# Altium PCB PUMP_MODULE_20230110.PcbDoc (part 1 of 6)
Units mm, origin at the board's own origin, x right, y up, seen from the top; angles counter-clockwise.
Board outline 260.15 x 142.01 mm, 4 copper layers (Top Layer, Mid-Layer 1, Mid-Layer 2, Bottom Layer); 422 components, 240 nets, 1746 pads, 416 vias.
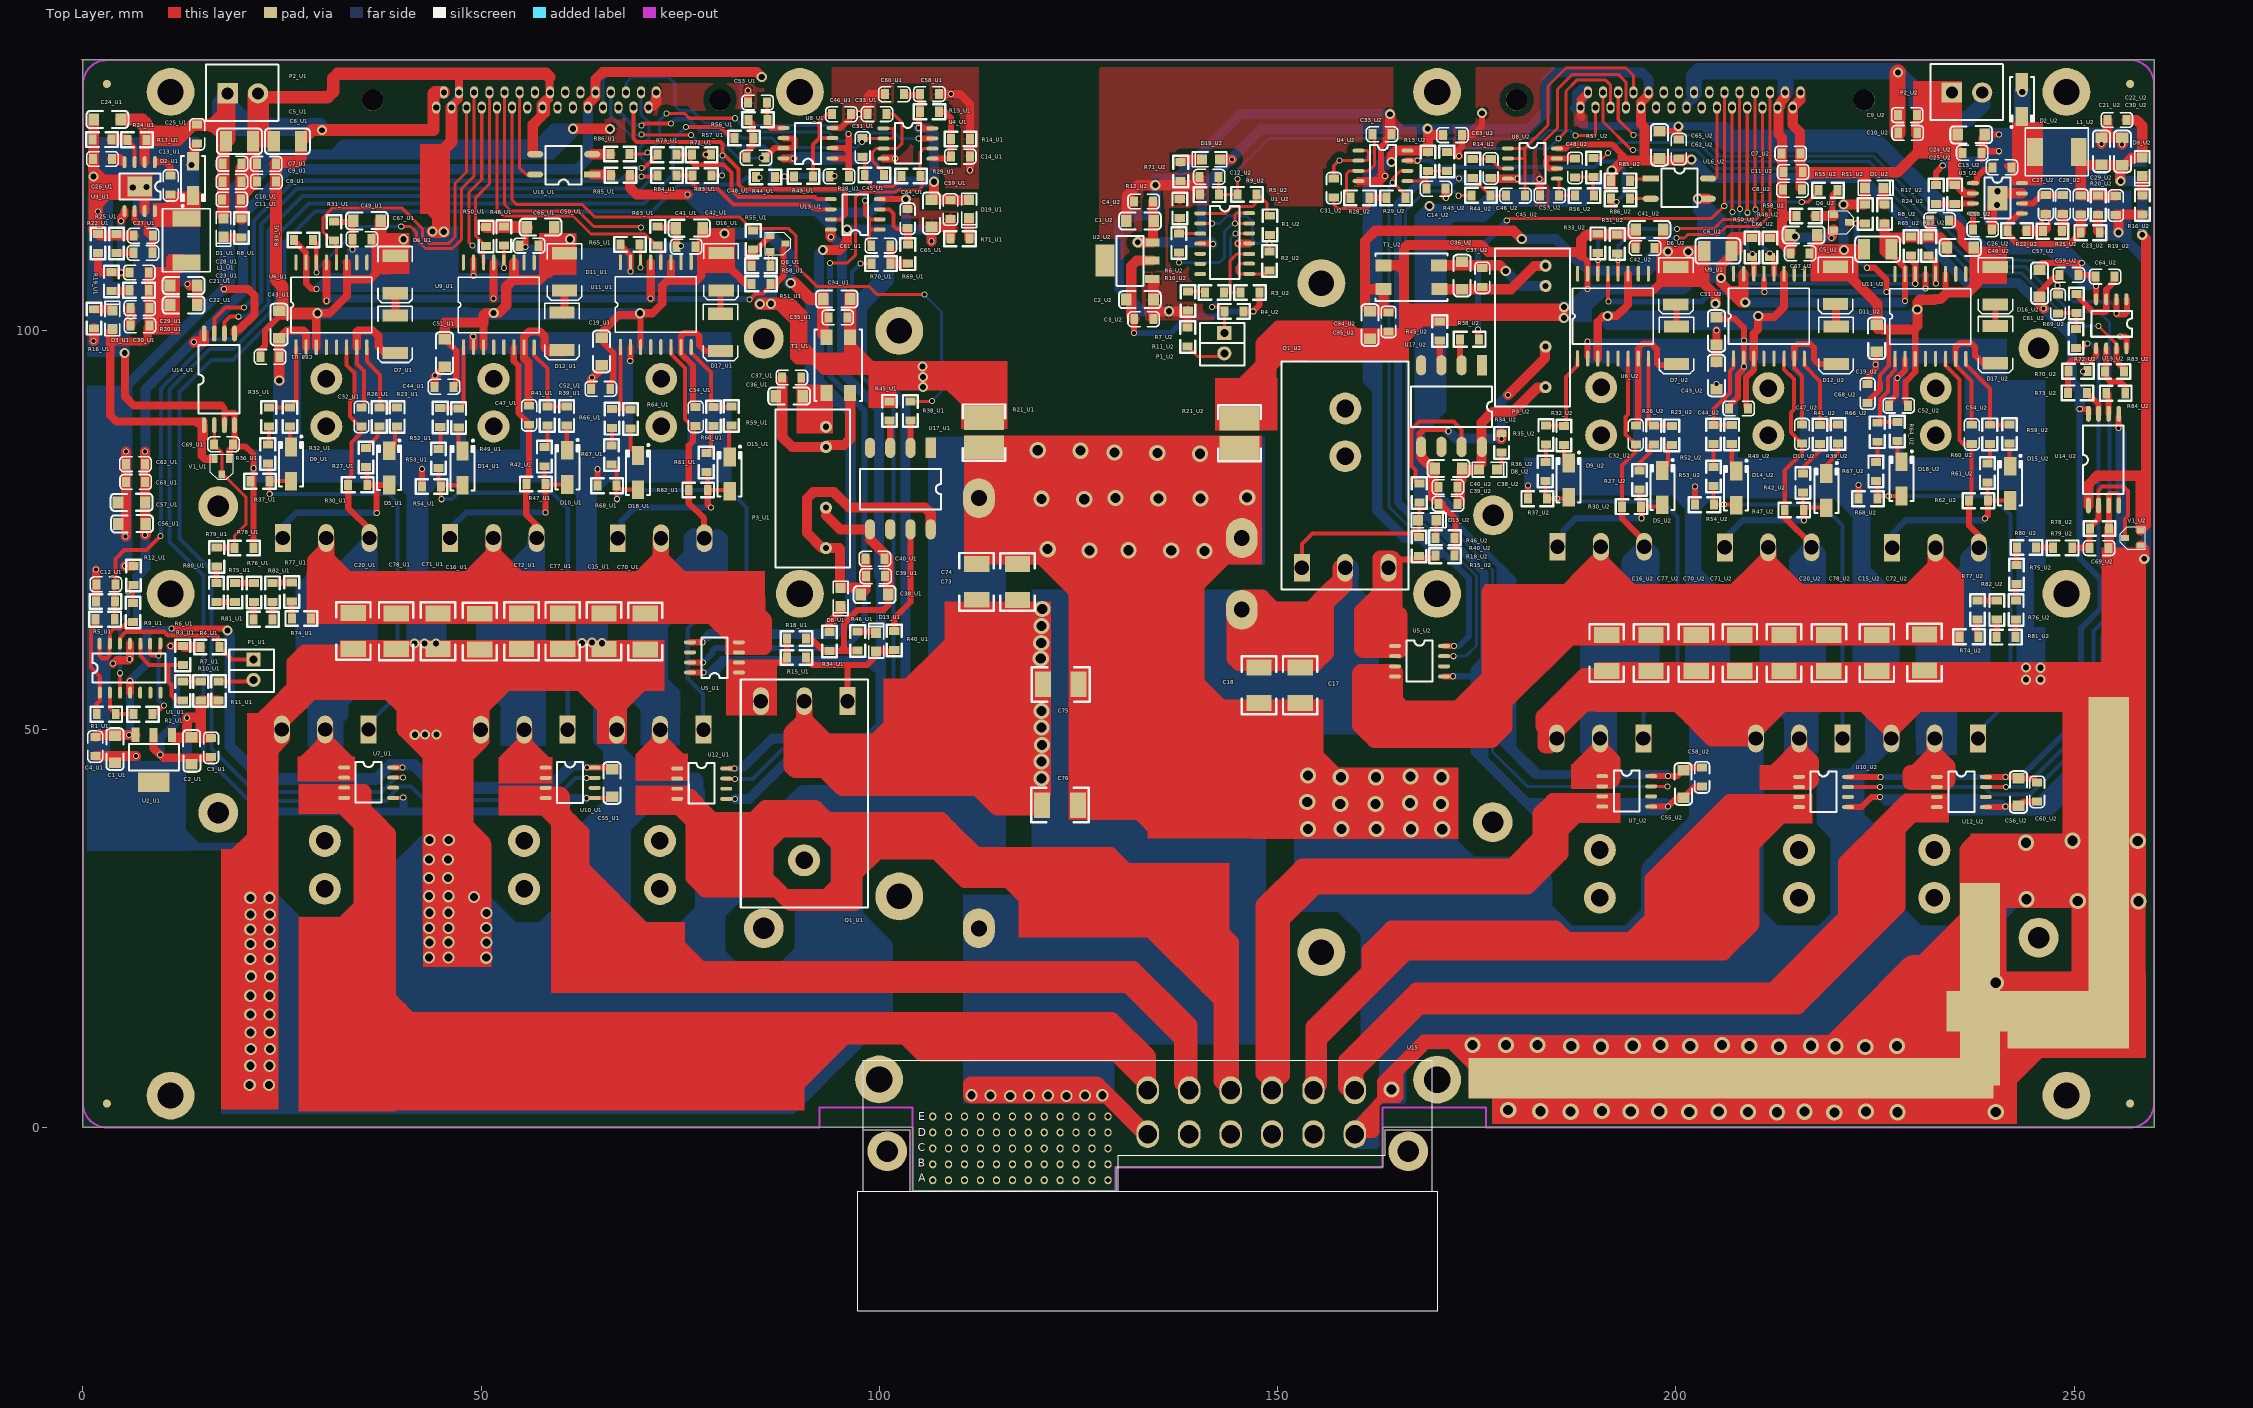
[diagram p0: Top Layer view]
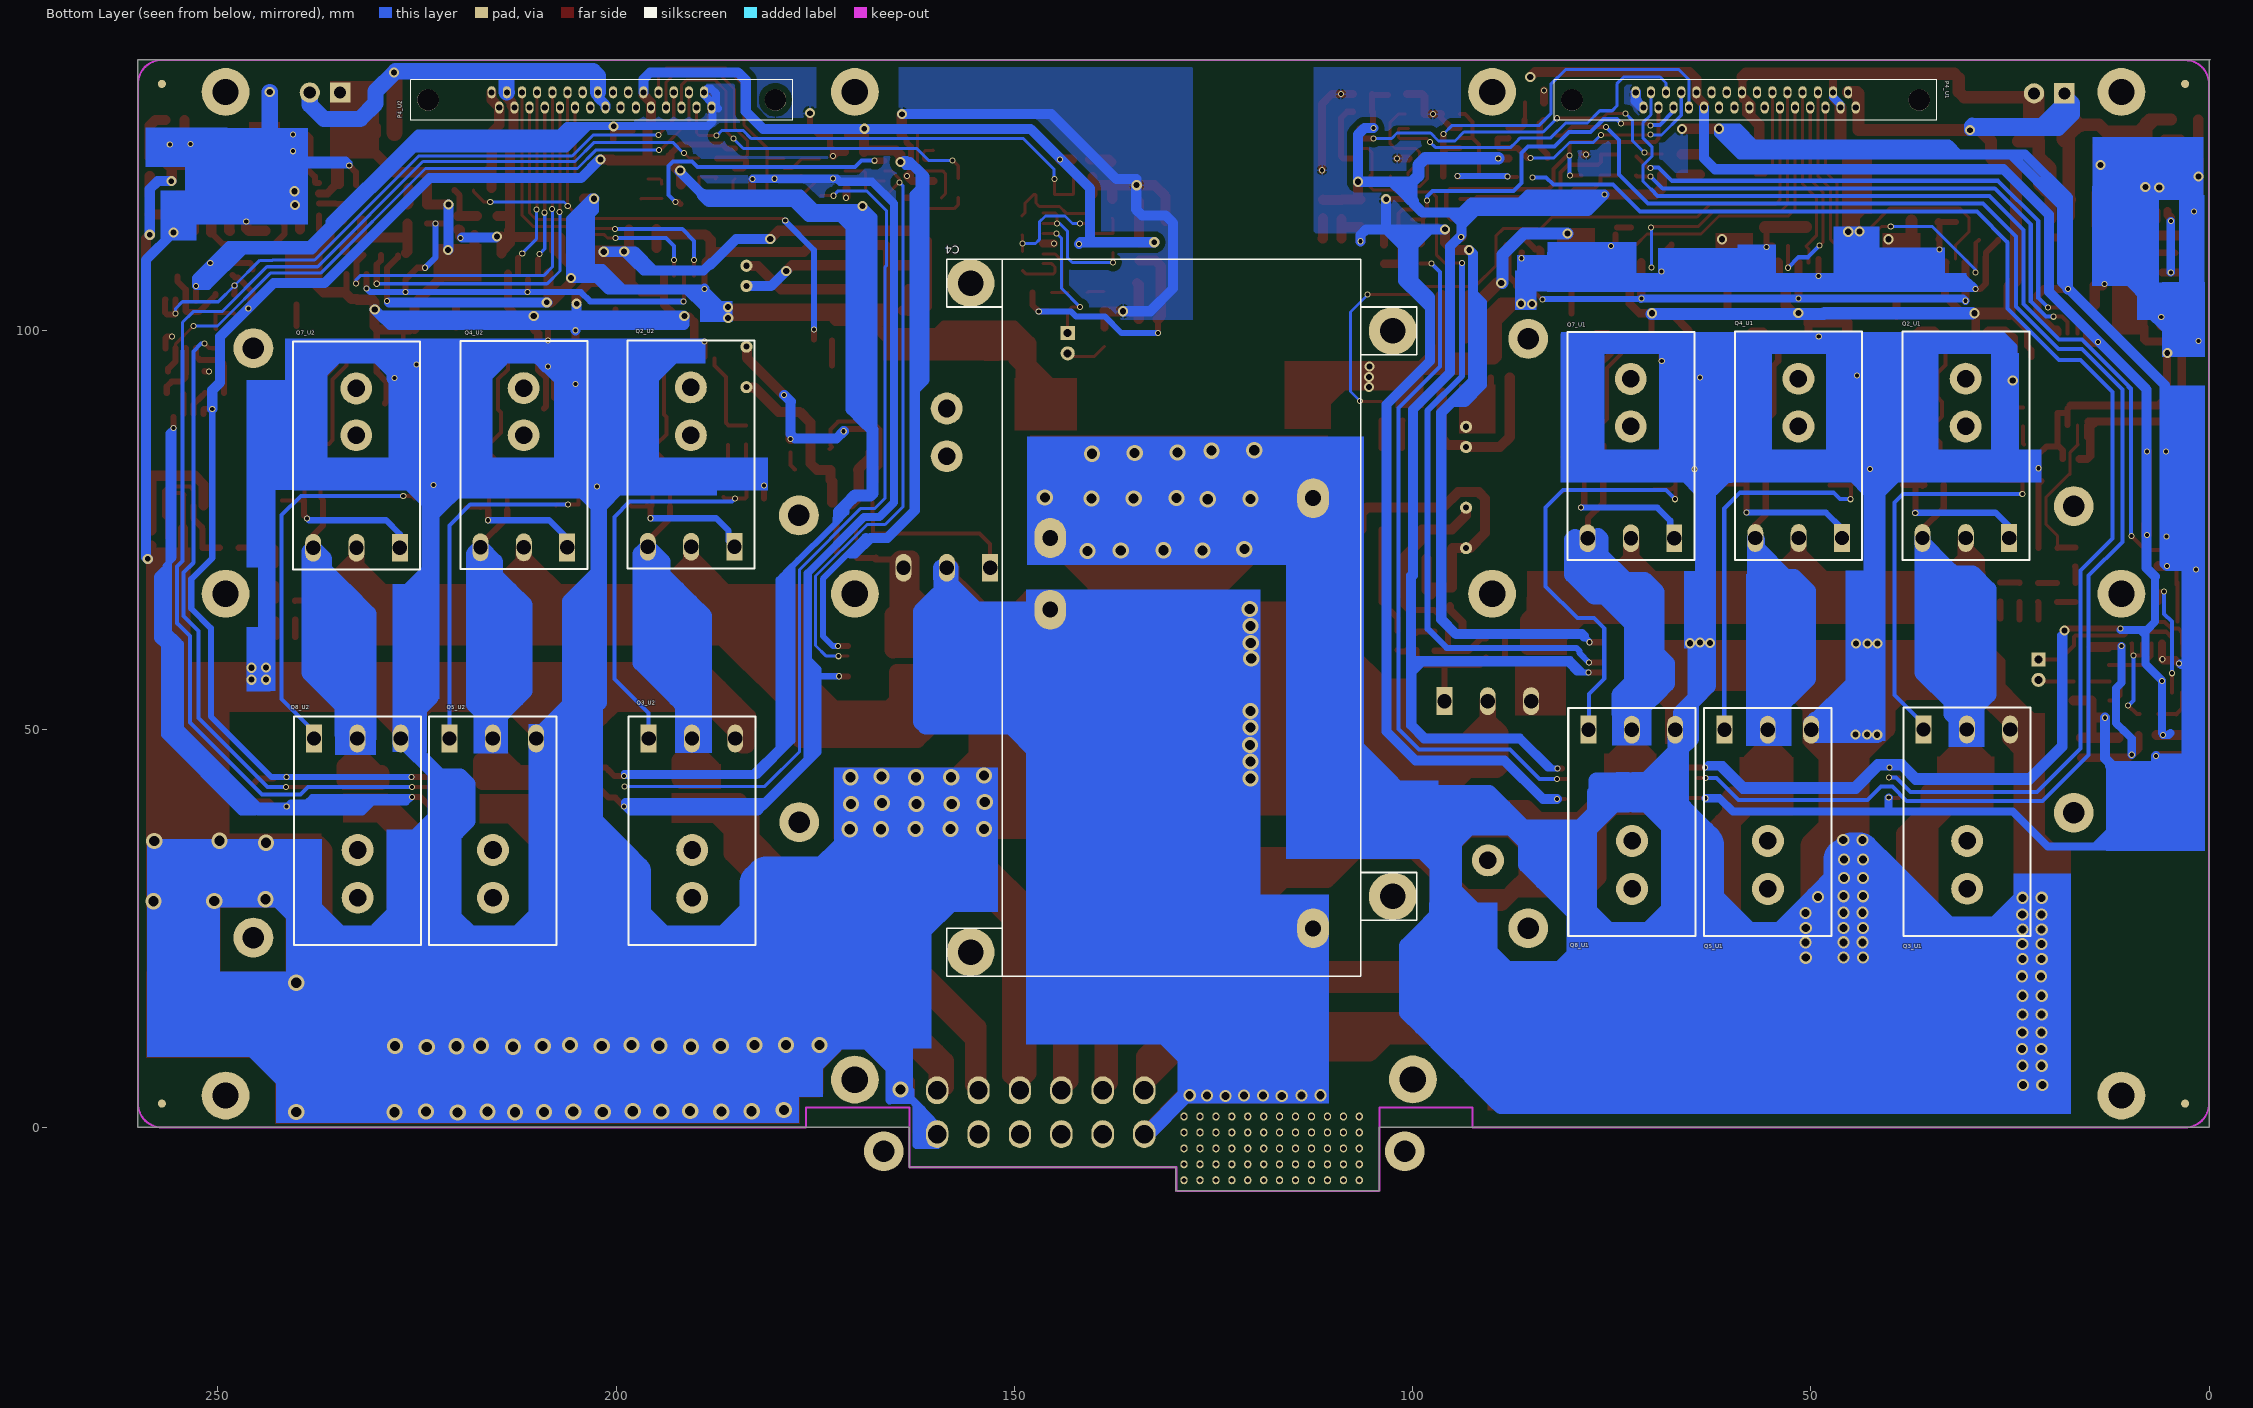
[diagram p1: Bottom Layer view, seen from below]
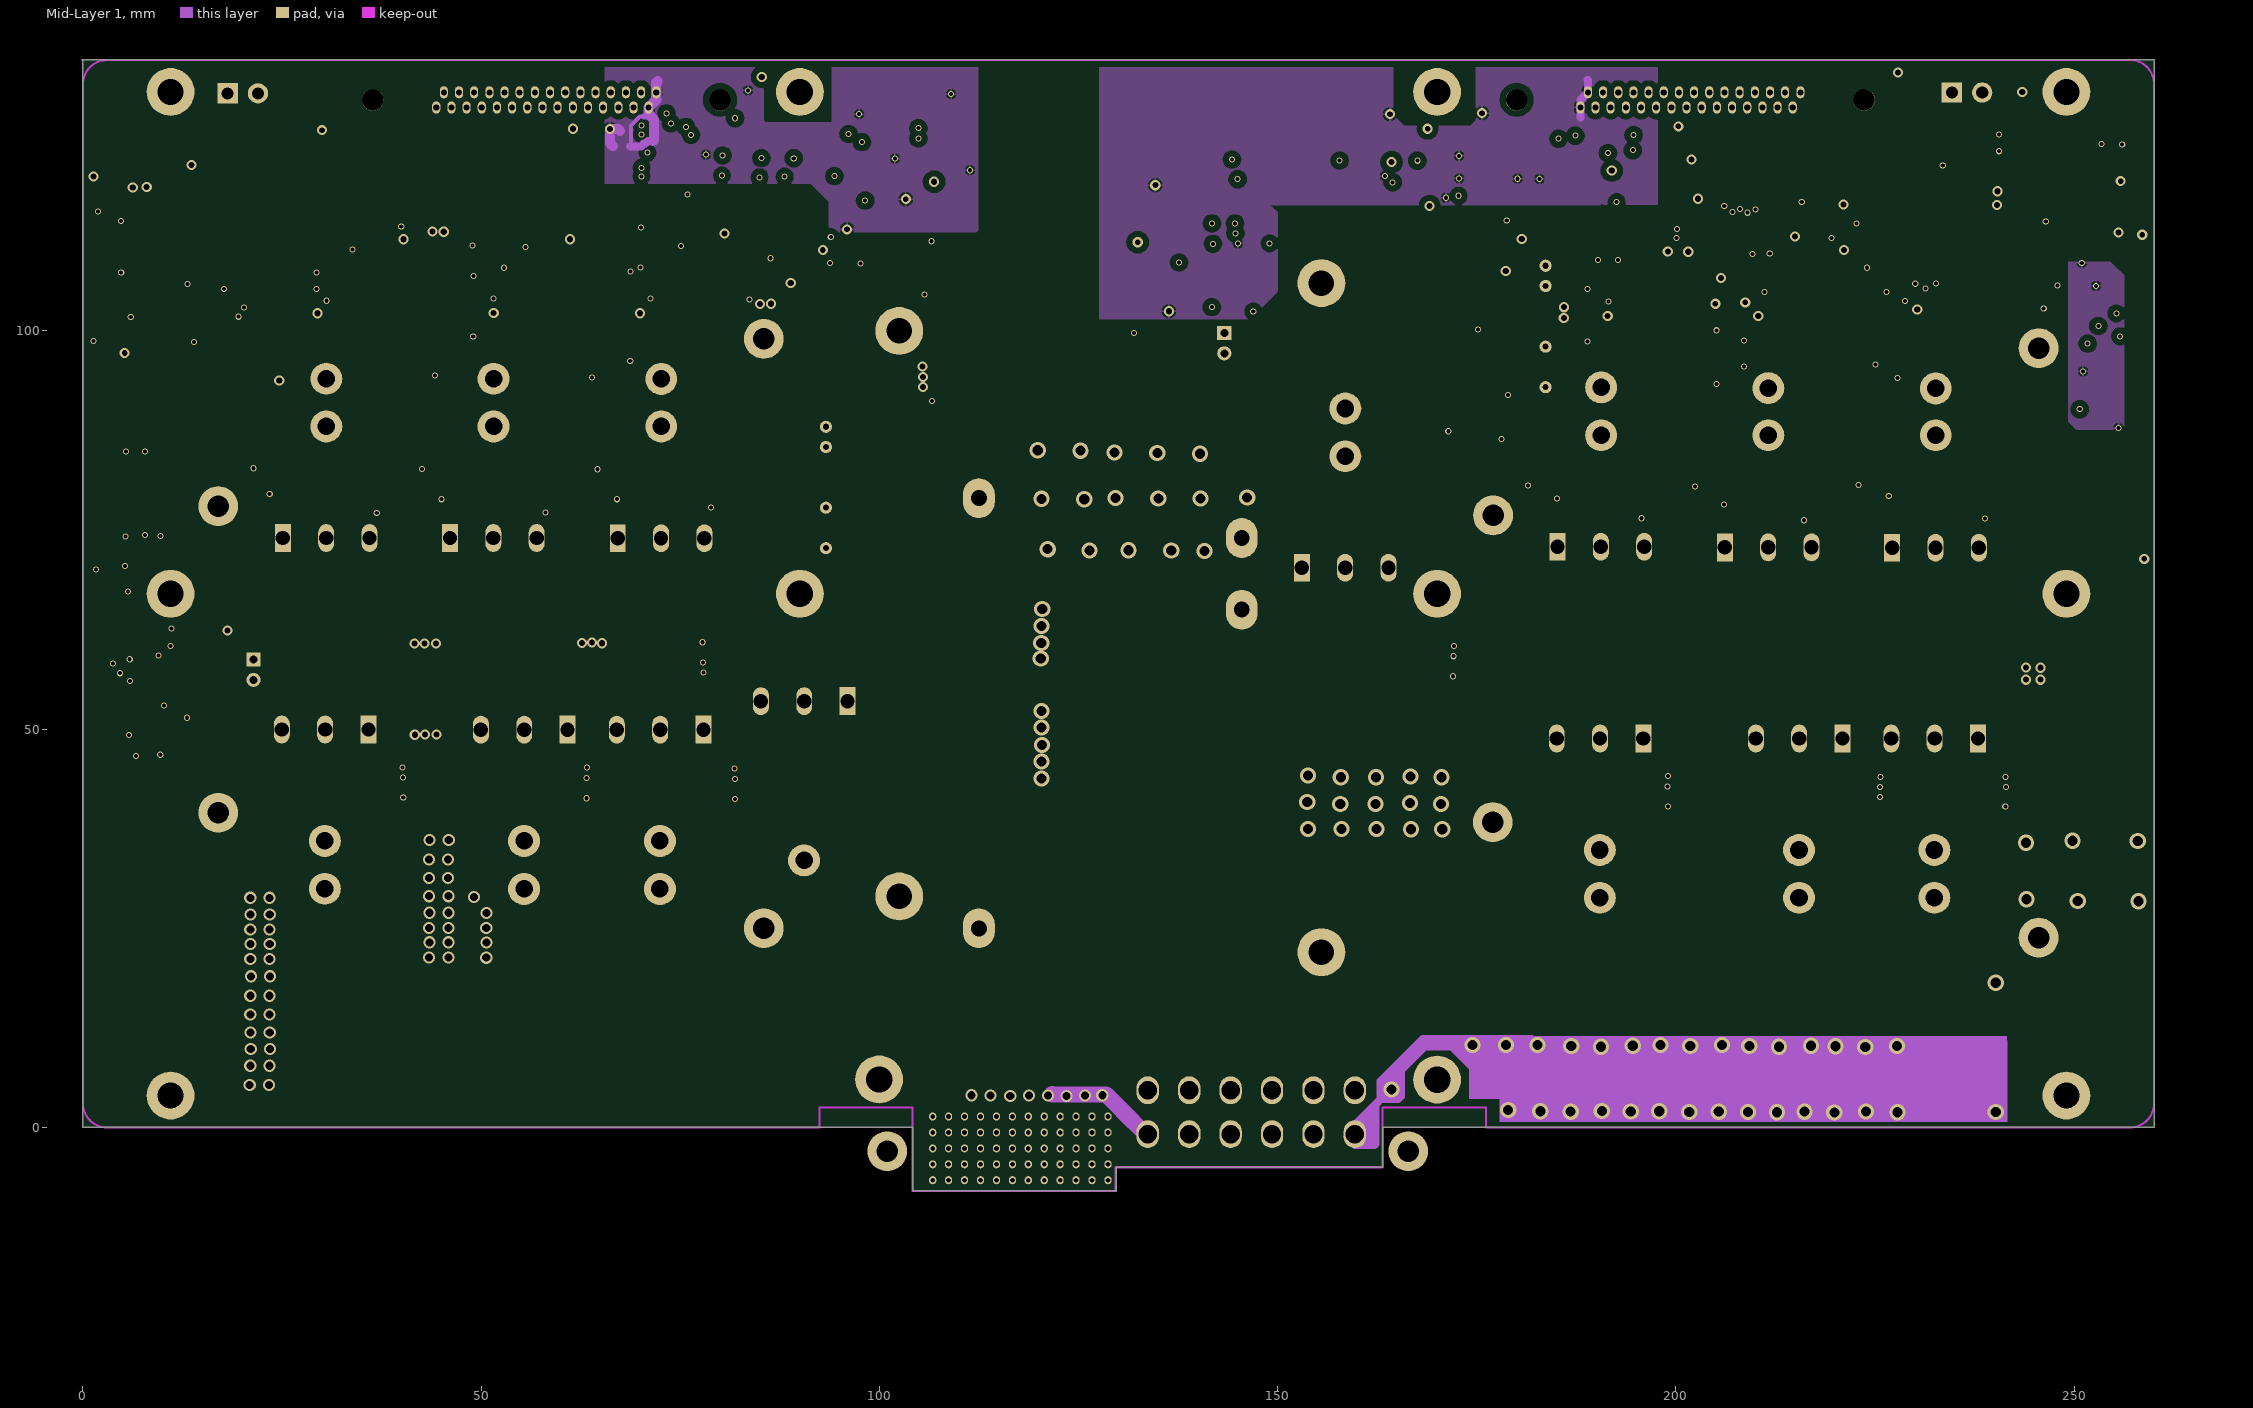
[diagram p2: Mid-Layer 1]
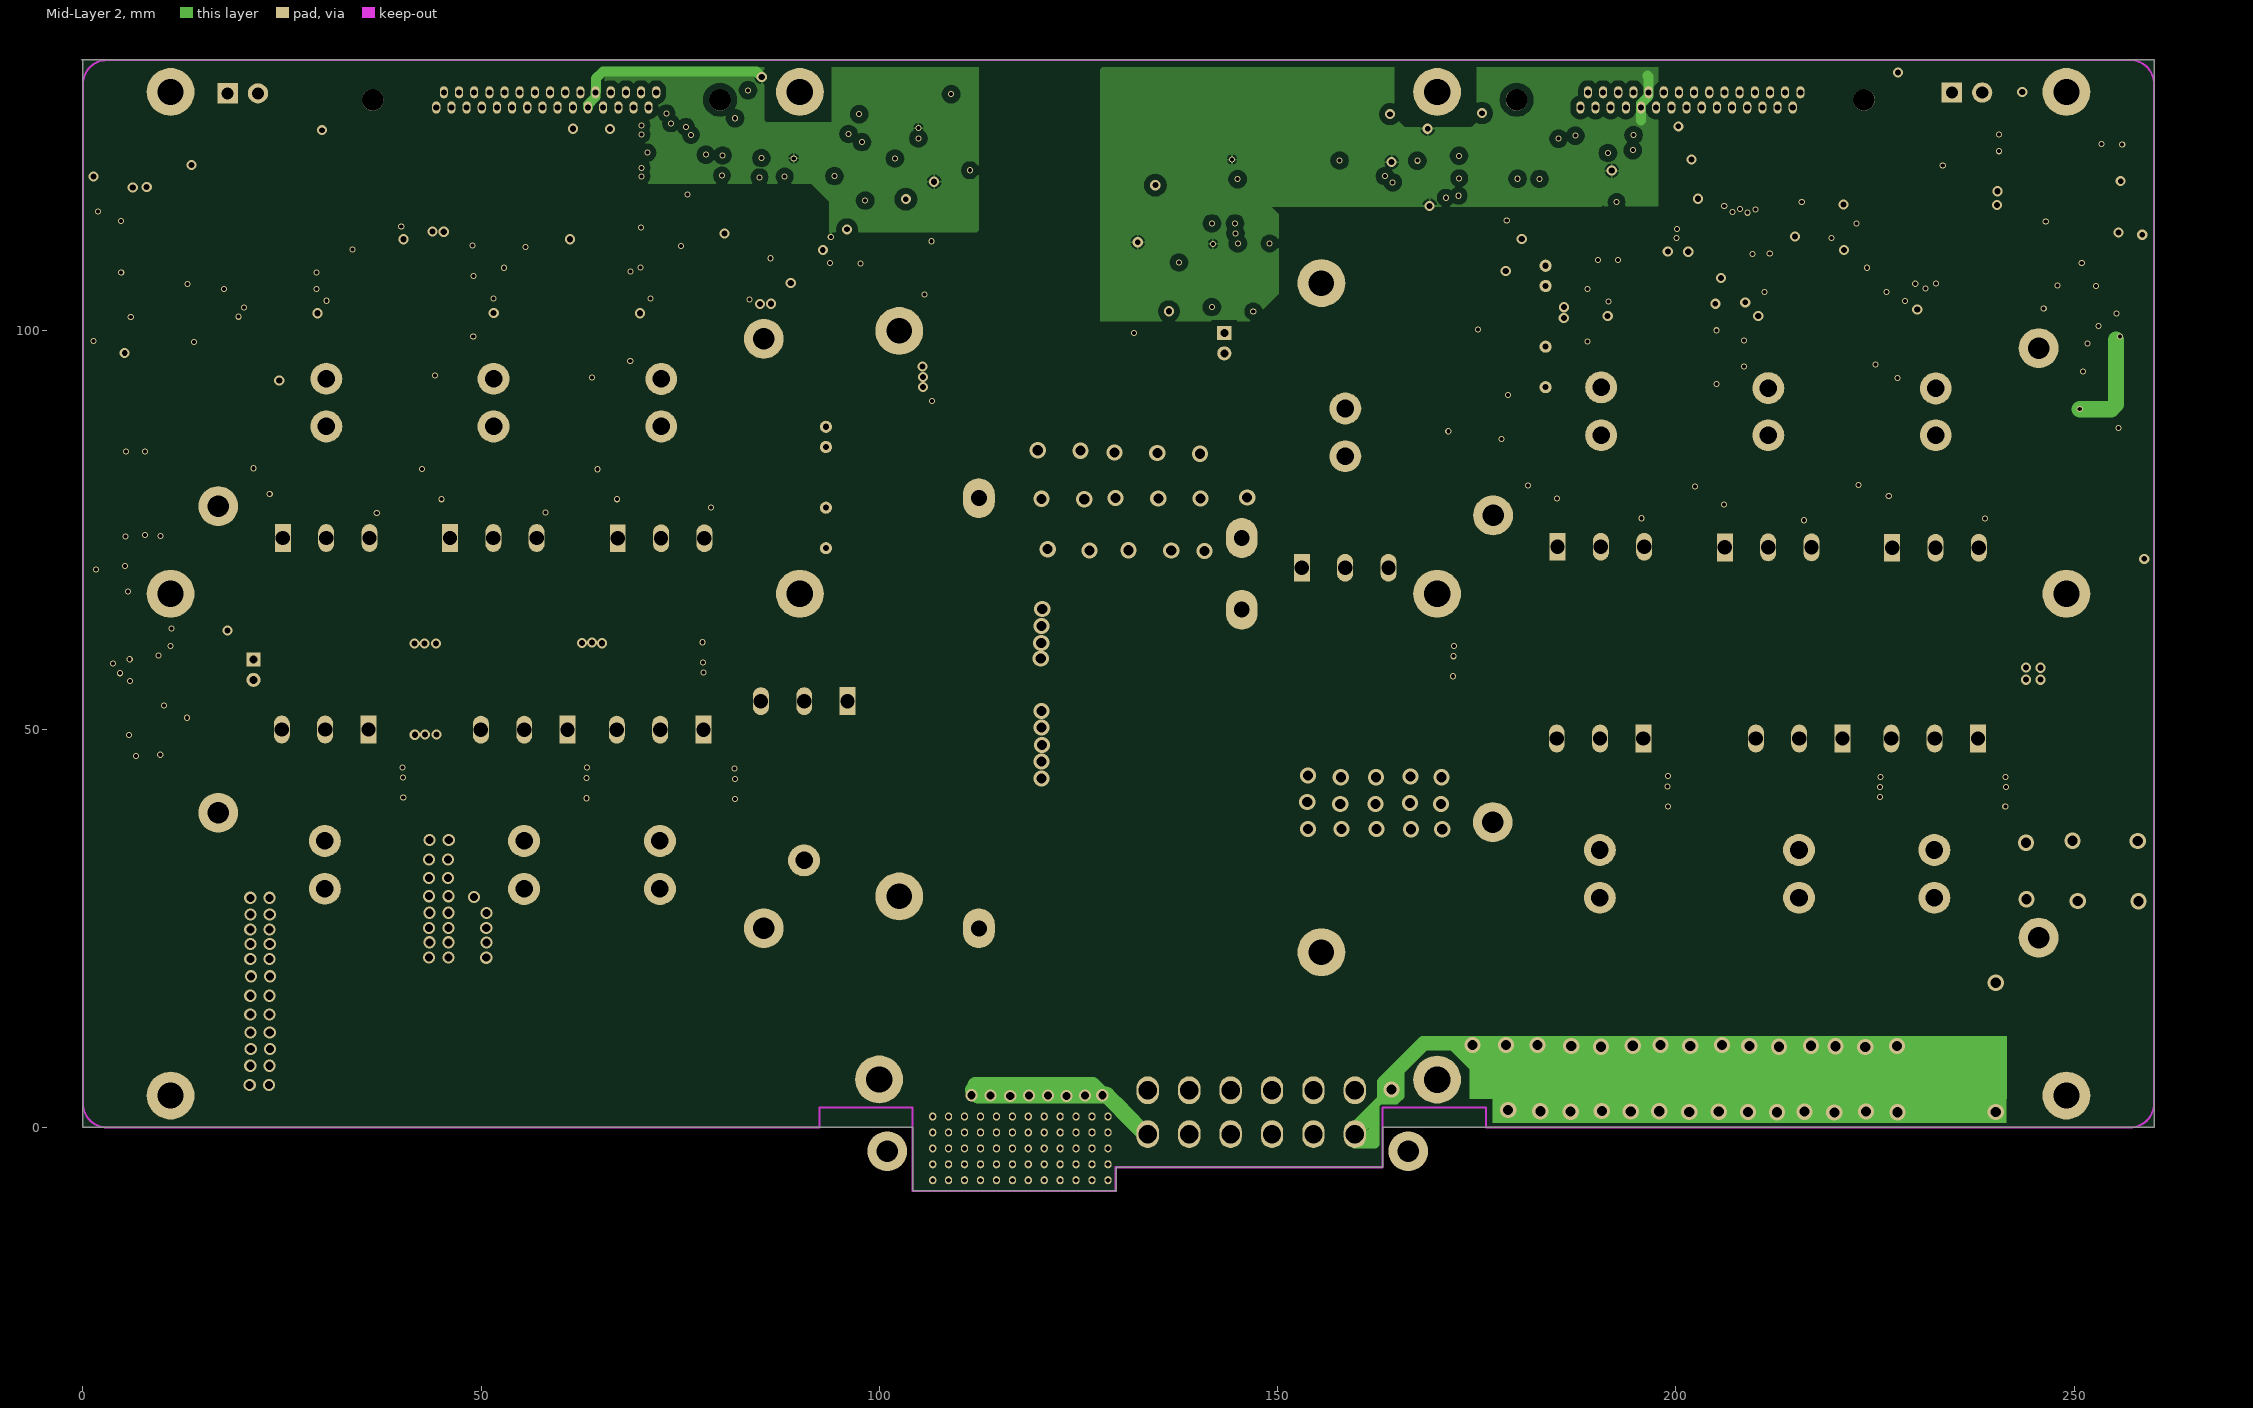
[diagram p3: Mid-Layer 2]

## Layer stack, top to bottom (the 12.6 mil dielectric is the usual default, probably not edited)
Top Layer: signal copper 0.0356
Dielectric: core 0.32, FR-4, Dk 4.8
Mid-Layer 1: signal copper 0.0356
Dielectric: prepreg 0.32, FR-4, Dk 4.8
Mid-Layer 2: signal copper 0.0356
Dielectric: core 0.32, FR-4, Dk 4.8
Bottom Layer: signal copper 0.0356

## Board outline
0,134.01 0.025,133.985 0.025,0 104.225,0 104.225,-7.925 129.649,-7.925 129.725,-8.001 129.725,-5 163.225,-5 163.225,0 260.045,0 260.045,134.01 -0.102,134.01

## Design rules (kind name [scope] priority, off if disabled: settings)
Clearance Clearance_1 [InPolygon] p1: gap=0.762
Clearance [All] p2: gap=0.254
HoleSize [All] p1: absolutevalues=TRUE maxlimit=12.7 minlimit=0.025 maxpercent=80.000 minpercent=20.000
MinimumSolderMaskSliver [All] p1: minsoldermaskwidth=0
PolygonConnect [All] p1: connectstyle=Relief reliefconductorwidth=0.254 reliefentries=4 polygonreliefangle="90 Angle" airgapwidth=0.254
RoutingVias [All] p1: holewidth=0.711 width=1.27 viastyle="Through Hole" minholewidth=0.508 minwidth=0.762 maxholewidth=0.711 maxwidth=1.27
SilkToSilkClearance [All] p1: silktosilkclearance=0
SilkToSolderMaskClearance [IsPad] p1: minsilkscreentomaskgap=0 clearancetoexposedcopper=TRUE
SolderMaskExpansion [All] p1: expansion=0.102
Width [All] p1: maxlimit=5.08 minlimit=0.254 preferedwidth=0.254 minimp=50.000000 maximp=50.000000 favimp=50.000000
24 further rules are at their usual default settings.

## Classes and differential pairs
channel class PUMP_THREEPHASE_MODULE: U1 U2
component class U3: C4 C17 C18 C73 C74 C75 C76 U15
component class U2: C1_U2 C2_U2 C3_U2 C4_U2 C5_U2 C6_U2 C7_U2 C8_U2 C9_U2 C10_U2 C11_U2 C12_U2 C13_U2 C14_U2 C15_U2 C16_U2 C19_U2 C20_U2 C21_U2 C22_U2 C23_U2 C24_U2 C25_U2 C26_U2 C27_U2 C28_U2 C29_U2 C30_U2 C31_U2 C32_U2 C33_U2 C34_U2 C35_U2 C36_U2 C37_U2 C38_U2 C39_U2 C40_U2 C41_U2 C42_U2 C43_U2 C44_U2 C45_U2 C46_U2 C47_U2 C48_U2 C49_U2 C50_U2 C51_U2 C52_U2 C53_U2 C54_U2 C55_U2 C56_U2 C57_U2 C58_U2 C59_U2 C60_U2 C61_U2 C62_U2 C63_U2 C64_U2 C65_U2 C66_U2 C67_U2 C68_U2 C69_U2 C70_U2 C71_U2 C72_U2 C77_U2 C78_U2 D1_U2 D2_U2 D3_U2 D5_U2 D6_U2 D7_U2 D8_U2 D9_U2 D10_U2 D11_U2 D12_U2 D13_U2 D14_U2 D15_U2 D16_U2 D17_U2 D18_U2 D19_U2 L1_U2 P1_U2 P2_U2 P3_U2 P4_U2 Q1_U2 Q2_U2 Q3_U2 Q4_U2 Q5_U2 Q6_U2 Q7_U2 Q8_U2 R1_U2 R2_U2 R3_U2 R4_U2 R5_U2 R6_U2 R7_U2 R8_U2 R9_U2 R10_U2 R11_U2 R12_U2 R13_U2 R14_U2 R15_U2 R16_U2 R17_U2 R18_U2 R19_U2 R20_U2 R21_U2 R22_U2 R23_U2 R24_U2 R25_U2 R26_U2 R27_U2 R28_U2 R29_U2 R30_U2 R31_U2 R32_U2 R33_U2 R34_U2 R35_U2 R36_U2 R37_U2 R38_U2 R39_U2 R40_U2 R41_U2 R42_U2 R43_U2 R44_U2 R45_U2 R46_U2 R47_U2 R48_U2 R49_U2 R50_U2 R51_U2 R52_U2 R53_U2 R54_U2 R55_U2 R56_U2 R57_U2 R58_U2 R59_U2 R60_U2 R61_U2 R62_U2 R63_U2 R64_U2 R65_U2 R66_U2 R67_U2 R68_U2 R69_U2 R70_U2 R71_U2 R72_U2 R73_U2 R74_U2 R75_U2 R76_U2 R77_U2 R78_U2 R79_U2 R80_U2 R81_U2 R82_U2 R83_U2 R84_U2 R85_U2 R86_U2 T1_U2 U1_U2 U2_U2 U3_U2 U4_U2 U5_U2 U6_U2 U7_U2 U8_U2 U9_U2 U10_U2 U11_U2 U12_U2 U13_U2 U14_U2 U16_U2 U17_U2 V1_U2
component class U1: C1_U1 C2_U1 C3_U1 C4_U1 C5_U1 C6_U1 C7_U1 C8_U1 C9_U1 C10_U1 C11_U1 C12_U1 C13_U1 C14_U1 C15_U1 C16_U1 C19_U1 C20_U1 C21_U1 C22_U1 C23_U1 C24_U1 C25_U1 C26_U1 C27_U1 C28_U1 C29_U1 C30_U1 C31_U1 C32_U1 C33_U1 C34_U1 C35_U1 C36_U1 C37_U1 C38_U1 C39_U1 C40_U1 C41_U1 C42_U1 C43_U1 C44_U1 C45_U1 C46_U1 C47_U1 C48_U1 C49_U1 C50_U1 C51_U1 C52_U1 C53_U1 C54_U1 C55_U1 C56_U1 C57_U1 C58_U1 C59_U1 C60_U1 C61_U1 C62_U1 C63_U1 C64_U1 C65_U1 C66_U1 C67_U1 C68_U1 C69_U1 C70_U1 C71_U1 C72_U1 C77_U1 C78_U1 D1_U1 D2_U1 D3_U1 D5_U1 D6_U1 D7_U1 D8_U1 D9_U1 D10_U1 D11_U1 D12_U1 D13_U1 D14_U1 D15_U1 D16_U1 D17_U1 D18_U1 D19_U1 L1_U1 P1_U1 P2_U1 P3_U1 P4_U1 Q1_U1 Q2_U1 Q3_U1 Q4_U1 Q5_U1 Q6_U1 Q7_U1 Q8_U1 R1_U1 R2_U1 R3_U1 R4_U1 R5_U1 R6_U1 R7_U1 R8_U1 R9_U1 R10_U1 R11_U1 R12_U1 R13_U1 R14_U1 R15_U1 R16_U1 R17_U1 R18_U1 R19_U1 R20_U1 R21_U1 R22_U1 R23_U1 R24_U1 R25_U1 R26_U1 R27_U1 R28_U1 R29_U1 R30_U1 R31_U1 R32_U1 R33_U1 R34_U1 R35_U1 R36_U1 R37_U1 R38_U1 R39_U1 R40_U1 R41_U1 R42_U1 R43_U1 R44_U1 R45_U1 R46_U1 R47_U1 R48_U1 R49_U1 R50_U1 R51_U1 R52_U1 R53_U1 R54_U1 R55_U1 R56_U1 R57_U1 R58_U1 R59_U1 R60_U1 R61_U1 R62_U1 R63_U1 R64_U1 R65_U1 R66_U1 R67_U1 R68_U1 R69_U1 R70_U1 R71_U1 R72_U1 R73_U1 R74_U1 R75_U1 R76_U1 R77_U1 R78_U1 R79_U1 R80_U1 R81_U1 R82_U1 R83_U1 R84_U1 R85_U1 R86_U1 T1_U1 U1_U1 U2_U1 U3_U1 U4_U1 U5_U1 U6_U1 U7_U1 U8_U1 U9_U1 U10_U1 U11_U1 U12_U1 U13_U1 U14_U1 U16_U1 U17_U1 V1_U1

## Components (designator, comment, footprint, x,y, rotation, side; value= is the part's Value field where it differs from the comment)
C1_U1 "22uF/25V" WP_1206CC 4.064,49.2 r270 top (schematic designator C1)
C1_U2 "22uF/25V" WP_1206CC 134.442,113.792 r180 top (schematic designator C1)
C2_U1 "22uF/25V" WP_1206CC 13.665,45.568 r90 top (schematic designator C2)
C2_U2 "22uF/25V" WP_1206CC 130.988,103.937 r0 top (schematic designator C2)
C3_U1 "0.1uF/50V" WP_0805C 16.078,46.457 r90 top (schematic designator C3)
C3_U2 "0.1uF/50V" WP_0805C 131.978,101.498 r0 top (schematic designator C3)
C4 "150uF/450V" MKP3D-450V-140UF-1 106.5,19 r90 bottom locked
C4_U1 "0.1uF/50V" WP_0805C 1.6,49.022 r270 top (schematic designator C4)
C4_U2 "0.1uF/50V" WP_0805C 134.391,116.205 r180 top (schematic designator C4)
C5_U1 "47uF/50V" WP_1210CC 27.407,123.8 r180 top (schematic designator C5)
C5_U2 "47uF/50V" WP_1210CC 223.622,110.261 r0 top (schematic designator C5)
C6_U1 "47uF/50V" WP_1210CC 17.958,123.8 r0 top (schematic designator C6)
C6_U2 "47uF/50V" WP_1210CC 203.556,110.033 r0 top (schematic designator C6)
C7_U1 "0.1uF/50V" WP_0805C 19.964,120.955 r180 top (schematic designator C7)
C7_U2 "0.1uF/50V" WP_0805C 213.208,122.301 r0 top (schematic designator C7)
C8_U1 "0.1uF/50V" WP_0805C 21.844,118.796 r0 top (schematic designator C8)
C8_U2 "0.1uF/50V" WP_0805C 213.436,117.754 r0 top (schematic designator C8)
C9_U1 "0.1uF/50V" WP_0805C 21.819,121.006 r0 top (schematic designator C9)
C9_U2 "0.1uF/50V" WP_0805C 227.838,127.127 r0 top (schematic designator C9)
C10_U1 "0.1uF/50V" WP_0805C 19.914,116.459 r180 top (schematic designator C10)
C10_U2 "0.1uF/50V" WP_0805C 227.889,124.892 r0 top (schematic designator C10)
C11_U1 "0.1uF/50V" WP_0805C 19.939,118.694 r180 top (schematic designator C11)
C11_U2 "0.1uF/50V" WP_0805C 213.512,119.99 r0 top (schematic designator C11)
C12_U1 "0.1uF/50V" WP_0805C 4.115,68.148 r180 top (schematic designator C12)
C12_U2 "0.1uF/50V" WP_0805C 142.621,119.304 r180 top (schematic designator C12)
C13_U1 "0.1uF/50V" WP_0805C 10.998,117.069 r90 top (schematic designator C13)
C13_U2 "0.1uF/50V" WP_0805C 242.138,120.498 r180 top (schematic designator C13)
C14_U1 "0.1uF/50V" WP_0805C 108.966,121.92 r0 top (schematic designator C14)
C14_U2 "0.1uF/50V" WP_0805C 168.681,117.881 r0 top (schematic designator C14)
C15_U1 "0.1uF/630V" WP_1812 65.43,60.198 r90 top (schematic designator C15)
C15_U2 "0.1uF/630V" WP_1812 225.222,57.48 r90 top (schematic designator C15)
C16_U1 "0.1uF/630V" WP_1812 49.835,60.147 r90 top (schematic designator C16)
C16_U2 "0.1uF/630V" WP_1812 191.313,57.455 r90 top (schematic designator C16)
C17 "0.1uF/630V" WP_1812 152.832,53.416 r90 top
C18 "0.1uF/630V" WP_1812 147.65,53.416 r90 top
C19_U1 "10uF/50V" WP_1206CC 65.151,99.136 r270 top (schematic designator C19)
C19_U2 "10uF/50V" WP_1206CC 225.222,100.787 r270 top (schematic designator C19)
C20_U1 "0.1uF/630V" WP_1812 33.96,60.223 r90 top (schematic designator C20)
C20_U2 "0.1uF/630V" WP_1812 213.563,57.48 r90 top (schematic designator C20)
C21_U1 "22uF/25V" WP_1206CC 10.947,105.715 r0 top (schematic designator C21)
C21_U2 "22uF/25V" WP_1206CC 253.416,120.828 r90 top (schematic designator C21)
C22_U1 "22uF/25V" WP_1206CC 10.947,103.251 r0 top (schematic designator C22)
C22_U2 "22uF/25V" WP_1206CC 256.032,120.802 r90 top (schematic designator C22)
C23_U1 "100pF/50V" WP_0805C 8.306,107.29 r180 top (schematic designator C23)
C23_U2 "100pF/50V" WP_0805C 250.85,117.043 r270 top (schematic designator C23)
C24_U1 "22uF/25V" WP_1206CC 4.801,126.517 r180 top (schematic designator C24)
C24_U2 "22uF/25V" WP_1206CC 235.356,124.638 r0 top (schematic designator C24)
C25_U1 "0.1uF/50V" WP_0805C 14.326,123.469 r90 top (schematic designator C25)
C25_U2 "0.1uF/50V" WP_0805C 238.404,122.326 r180 top (schematic designator C25)
C26_U1 "0.01uF/50V" WP_0805C 1.27,121.615 r0 top (schematic designator C26)
C26_U2 "0.01uF/50V" WP_0805C 239.725,112.725 r180 top (schematic designator C26)
C27_U1 "22pF/50V" WP_0805C 6.375,111.989 r0 top (schematic designator C27)
C27_U2 "22pF/50V" WP_0805C 246.405,114.656 r90 top (schematic designator C27)
C28_U1 "2.2nF/50V" WP_0805C 6.35,109.83 r0 top (schematic designator C28)
C28_U2 "2.2nF/50V" WP_0805C 248.539,114.656 r90 top (schematic designator C28)
C29_U1 "0.1uF/50V" WP_0805C 5.944,102.895 r0 top (schematic designator C29)
C29_U2 "0.1uF/50V" WP_0805C 255.194,114.529 r90 top (schematic designator C29)
C30_U1 "0.1uF/50V" WP_0805C 5.969,100.711 r0 top (schematic designator C30)
C30_U2 "0.1uF/50V" WP_0805C 254.152,126.517 r0 top (schematic designator C30)
C31_U1 "10nF/50V" WP_0805C 97.866,121.818 r90 top (schematic designator C31)
C31_U2 "10nF/50V" WP_0805C 157.023,116.713 r90 top (schematic designator C31)
C32_U1 "1uF/50V" WP_0805C 35.027,90.399 r270 top (schematic designator C32)
C32_U2 "1uF/50V" WP_0805C 194.996,88.138 r270 top (schematic designator C32)
C33_U1 "3.3nF/50V" WP_0805C 100.914,127.178 r180 top (schematic designator C33)
C33_U2 "3.3nF/50V" WP_0805C 161.9,124.714 r0 top (schematic designator C33)
C34_U1 "" WP_1206CC 92.939,104.013 r0 top (schematic designator C34)
C34_U2 "" WP_1206CC 161.62,102.438 r270 top (schematic designator C34)
C35_U1 "" WP_0805C 93.574,101.727 r0 top (schematic designator C35)
C35_U2 "" WP_0805C 163.957,102.337 r270 top (schematic designator C35)
C36_U1 "22uF/25V" WP_1206CC 90.399,91.796 r180 top (schematic designator C36)
C36_U2 "22uF/25V" WP_1206CC 173.152,105.232 r90 top (schematic designator C36)
C37_U1 "" WP_0805C 90.221,94.107 r180 top (schematic designator C37)
C37_U2 "" WP_0805C 175.666,105.461 r90 top (schematic designator C37)
C38_U1 "22uF/25V" WP_1206CC 97.688,66.904 r0 top (schematic designator C38)
C38_U2 "22uF/25V" WP_1206CC 173.177,82.702 r180 top (schematic designator C38)
C39_U1 "" WP_0805C 98.323,69.24 r0 top (schematic designator C39)
C39_U2 "" WP_0805C 172.593,78.257 r180 top (schematic designator C39)
C40_U1 "" WP_0805C 98.247,71.425 r0 top (schematic designator C40)
C40_U2 "" WP_0805C 172.593,80.366 r180 top (schematic designator C40)
C41_U1 "10uF/50V" WP_1206CC 77.851,112.878 r180 top (schematic designator C41)
C41_U2 "10uF/50V" WP_1206CC 198.399,112.725 r180 top (schematic designator C41)
C42_U1 "0.1uF/50V" WP_0805C 76.962,110.541 r180 top (schematic designator C42)
C42_U2 "0.1uF/50V" WP_0805C 197.333,110.363 r180 top (schematic designator C42)
C43_U1 "10uF/50V" WP_1206CC 24.663,102.514 r270 top (schematic designator C43)
C43_U2 "10uF/50V" WP_1206CC 205.105,96.114 r270 top (schematic designator C43)
C44_U1 "0.1uF/50V" WP_0805C 46.558,92.939 r180 top (schematic designator C44)
C44_U2 "0.1uF/50V" WP_0805C 209.093,90.221 r180 top (schematic designator C44)
C45_U1 "10nF/50V" WP_0805C 93.751,119.431 r0 top (schematic designator C45)
C45_U2 "10nF/50V" WP_0805C 178.664,117.018 r0 top (schematic designator C45)
C46_U1 "3.3nF/50V" WP_0805C 94.031,127.229 r0 top (schematic designator C46)
C46_U2 "3.3nF/50V" WP_0805C 176.784,121.59 r270 top (schematic designator C46)
C47_U1 "Cap Semi" WP_0805C 56.007,88.189 r90 top (schematic designator C47)
C47_U2 "Cap Semi" WP_0805C 215.798,85.827 r90 top (schematic designator C47)
C48_U1 "10nF/50V" WP_0805C 83.312,121.768 r0 top (schematic designator C48)
C48_U2 "10nF/50V" WP_0805C 187.3,119.253 r90 top (schematic designator C48)
C49_U1 "10uF/50V" WP_1206CC 37.389,113.817 r180 top (schematic designator C49)
C49_U2 "10uF/50V" WP_1206CC 237.414,110.465 r180 top (schematic designator C49)
C50_U1 "0.1uF/50V" WP_0805C 57.252,110.668 r180 top (schematic designator C50)
C50_U2 "0.1uF/50V" WP_0805C 234.315,113.843 r180 top (schematic designator C50)
C51_U1 "10uF/50V" WP_1206CC 45.441,98.933 r270 top (schematic designator C51)
C51_U2 "10uF/50V" WP_1206CC 205.08,98.273 r90 top (schematic designator C51)
C52_U1 "0.1uF/50V" WP_0805C 66.243,92.685 r180 top (schematic designator C52)
C52_U2 "0.1uF/50V" WP_0805C 229.184,90.576 r180 top (schematic designator C52)
C53_U1 "3.3nF/50V" WP_0805C 85.928,128.626 r180 top (schematic designator C53)
C53_U2 "3.3nF/50V" WP_0805C 185.369,116.967 r180 top (schematic designator C53)
C54_U1 "Cap Semi" WP_0805C 76.911,88.011 r90 top (schematic designator C54)
C54_U2 "Cap Semi" WP_0805C 237.109,85.801 r90 top (schematic designator C54)
C55_U1 "22uF/25V" WP_1206CC 66.472,44.958 r270 top (schematic designator C55)
C55_U2 "22uF/25V" WP_1206CC 200.939,44.831 r270 top (schematic designator C55)
C56_U1 "22uF/25V" WP_1206CC 7.899,75.768 r180 top (schematic designator C56)
C56_U2 "22uF/25V" WP_1206CC 243.027,43.815 r270 top (schematic designator C56)
C57_U1 "22uF/25V" WP_1206CC 7.849,78.461 r180 top (schematic designator C57)
C57_U2 "22uF/25V" WP_1206CC 245.643,104.267 r90 top (schematic designator C57)
C58_U1 "0.1uF/50V" WP_0805C 107.493,129.692 r180 top (schematic designator C58)
C58_U2 "0.1uF/50V" WP_0805C 203.251,42.748 r90 top (schematic designator C58)
C59_U1 "0.1uF/50V" WP_0805C 108.89,114.021 r90 top (schematic designator C59)
C59_U2 "0.1uF/50V" WP_0805C 250.546,106.985 r180 top (schematic designator C59)
C60_U1 "0.1uF/50V" WP_0805C 100.686,129.743 r0 top (schematic designator C60)
C60_U2 "0.1uF/50V" WP_0805C 245.313,40.919 r90 top (schematic designator C60)
C61_U1 "10nF/50V" WP_0805C 101.397,110.668 r180 top (schematic designator C61)
C61_U2 "10nF/50V" WP_0805C 247.929,102.133 r90 top (schematic designator C61)
C62_U1 "1uF/50V" WP_0805C 7.823,83.236 r180 top (schematic designator C62)
C62_U2 "1uF/50V" WP_0805C 200.33,121.615 r90 top (schematic designator C62)
C63_U1 "0.1uF/50V" WP_0805C 7.849,81.001 r180 top (schematic designator C63)
C63_U2 "0.1uF/50V" WP_0805C 170.739,124.612 r0 top (schematic designator C63)
C64_U1 "3.3nF/50V" WP_0805C 103.505,112.878 r90 top (schematic designator C64)
C64_U2 "3.3nF/50V" WP_0805C 255.092,106.782 r180 top (schematic designator C64)
C65_U1 "22uF/25V" WP_1206CC 106.553,116.484 r270 top (schematic designator C65)
C65_U2 "22uF/25V" WP_1206CC 197.942,121.641 r90 top (schematic designator C65)
C66_U1 "10uF/50V" WP_1206CC 59.182,113.005 r180 top (schematic designator C66)
C66_U2 "10uF/50V" WP_1206CC 217.754,112.039 r180 top (schematic designator C66)
C67_U1 "0.1uF/50V" WP_0805C 36.246,111.481 r180 top (schematic designator C67)
C67_U2 "0.1uF/50V" WP_0805C 216.814,109.703 r180 top (schematic designator C67)
C68_U1 "0.1uF/50V" WP_0805C 22.301,96.774 r0 top (schematic designator C68)
C68_U2 "0.1uF/50V" WP_0805C 224.028,90.907 r90 top (schematic designator C68)
C69_U1 "1nF/50V" WP_0805C 18.872,85.725 r180 top (schematic designator C69)
C69_U2 "1nF/50V" WP_0805C 254.33,72.695 r180 top (schematic designator C69)
C70_U1 "0.1uF/630V" WP_1812 70.612,60.173 r90 top (schematic designator C70)
C70_U2 "0.1uF/630V" WP_1812 202.54,57.455 r90 top (schematic designator C70)
C71_U1 "0.1uF/630V" WP_1812 44.602,60.198 r90 top (schematic designator C71)
C71_U2 "0.1uF/630V" WP_1812 208.026,57.455 r90 top (schematic designator C71)
C72_U1 "0.1uF/630V" WP_1812 55.067,60.198 r90 top (schematic designator C72)
C72_U2 "0.1uF/630V" WP_1812 231.216,57.531 r90 top (schematic designator C72)
C73 "0.1uF/630V" WP_1812 112.217,70.587 r270 top
C74 "0.1uF/630V" WP_1812 117.348,70.561 r270 top
C75 "0.1uF/630V" WP_1812 124.866,55.626 r180 top
C76 "0.1uF/630V" WP_1812 124.79,40.462 r180 top
C77_U1 "0.1uF/630V" WP_1812 60.249,60.198 r90 top (schematic designator C77)
C77_U2 "0.1uF/630V" WP_1812 196.875,57.455 r90 top (schematic designator C77)
C78_U1 "0.1uF/630V" WP_1812 39.345,60.198 r90 top (schematic designator C78)
C78_U2 "0.1uF/630V" WP_1812 219.202,57.455 r90 top (schematic designator C78)
D1_U1 "" WP_0805_LED 17.678,114.122 r270 top (schematic designator D1)
D1_U2 "" WP_0805_LED 223.749,117.958 r0 top (schematic designator D1)
D2_U1 "1N5822" WP_SMA_DO214AC 13.843,121.285 r270 top (schematic designator D2)
D2_U2 "1N5822" WP_SMA_DO214AC 243.434,131.216 r270 top (schematic designator D2)
D3_U1 "LED" WP_0805_LED 3.708,100.228 r90 top (schematic designator D3)
D3_U2 "LED" WP_0805_LED 258.547,121.742 r270 top (schematic designator D3)
D5_U1 "1N5822" WP_SMA_DO214AC 38.456,80.645 r90 top (schematic designator D5)
D5_U2 "1N5822" WP_SMA_DO214AC 198.298,78.181 r90 top (schematic designator D5)
D6_U1 "STTH112U" WP_1812D 39.218,109.423 r270 top (schematic designator D6)
D6_U2 "STTH112U" WP_1812D 200,108.026 r270 top (schematic designator D6)
D7_U1 "STTH112U" WP_1812D 39.218,101.93 r270 top (schematic designator D7)
D7_U2 "STTH112U" WP_1812D 200.076,100.533 r270 top (schematic designator D7)
D8_U1 "LED" WP_0805_LED 95.148,67.742 r270 top (schematic designator D8)
D8_U2 "LED" WP_0805_LED 175.26,82.601 r0 top (schematic designator D8)
D9_U1 "1N5822" WP_SMA_DO214AC 26.137,81.128 r90 top (schematic designator D9)
D9_U2 "1N5822" WP_SMA_DO214AC 186.538,79.121 r90 top (schematic designator D9)
D10_U1 "1N5822" WP_SMA_DO214AC 60.833,80.721 r90 top (schematic designator D10)
D10_U2 "1N5822" WP_SMA_DO214AC 218.897,77.8 r90 top (schematic designator D10)
D11_U1 "STTH112U" WP_1812D 60.477,109.753 r270 top (schematic designator D11)
D11_U2 "STTH112U" WP_1812D 220.04,108.052 r270 top (schematic designator D11)
D12_U1 "STTH112U" WP_1812D 60.173,102.286 r270 top (schematic designator D12)
D12_U2 "STTH112U" WP_1812D 220.116,100.533 r270 top (schematic designator D12)
D13_U1 "LED" WP_0805_LED 99.593,59.766 r90 top (schematic designator D13)
D13_U2 "LED" WP_0805_LED 167.64,76.225 r0 top (schematic designator D13)
D14_U1 "1N5822" WP_SMA_DO214AC 47.676,80.62 r90 top (schematic designator D14)
D14_U2 "1N5822" WP_SMA_DO214AC 207.569,78.105 r90 top (schematic designator D14)
D15_U1 "1N5822" WP_SMA_DO214AC 81.204,79.858 r90 top (schematic designator D15)
D15_U2 "1N5822" WP_SMA_DO214AC 241.96,78.715 r90 top (schematic designator D15)
D16_U1 "STTH112U" WP_1812D 80.137,109.779 r270 top (schematic designator D16)
D16_U2 "STTH112U" WP_1812D 240.106,108.026 r270 top (schematic designator D16)
D17_U1 "STTH112U" WP_1812D 80.061,102.159 r270 top (schematic designator D17)
D17_U2 "STTH112U" WP_1812D 240.106,100.635 r270 top (schematic designator D17)
D18_U1 "1N5822" WP_SMA_DO214AC 69.698,80.061 r90 top (schematic designator D18)
D18_U2 "1N5822" WP_SMA_DO214AC 228.321,79.273 r90 top (schematic designator D18)
D19_U1 "LED" WP_0805_LED 111.277,116.459 r270 top (schematic designator D19)
D19_U2 "LED" WP_0805_LED 142.799,121.514 r180 top (schematic designator D19)
L1_U1 "10uH/2A" WP_LBS6*6 13.005,108.61 r90 top (schematic designator L1)
L1_U2 "10uH/2A" WP_LBS6*6 250.571,122.479 r180 top (schematic designator L1)
P1_U1 "Header 2" WP_SIP2 21.438,58.725 r270 top (schematic designator P1)
P1_U2 "Header 2" WP_SIP2 143.307,99.72 r270 top (schematic designator P1)
P2_U1 "Header 2" WP_LSIP2 18.186,129.819 r0 top (schematic designator P2)
P2_U2 "Header 2" WP_LSIP2 234.645,129.921 r0 top (schematic designator P2)
P3_U1 "H1515S-2W" DC12-12 93.294,87.96 r270 top (schematic designator P2)
P3_U2 "H1515S-2W" DC12-12 183.642,108.179 r270 top (schematic designator P2)
P4_U1 "Header 15X2A" WP_CRM222-030 44.374,128.047 r180 bottom locked (schematic designator P4)
P4_U2 "Header 15X2A" WP_CRM222-030 215.623,129.952 r0 bottom locked (schematic designator P4)
Q1_U1 "IPW65R019C7" WP_TO247P#1 96.012,53.518 r180 top locked
Q1_U2 "IPW65R019C7" WP_TO247P#1 153.035,70.256 r0 top
Q2_U1 "IPW65R019C7" WP_TO247P#2 25.12,74 r0 bottom locked
Q2_U2 "IPW65R019C7" WP_TO247P#2 185.141,72.898 r0 bottom locked
Q3_U1 "IPW65R019C7" WP_TO247P#2 35.865,49.962 r180 bottom
Q3_U2 "IPW65R019C7" WP_TO247P#2 195.921,48.83 r180 bottom locked
Q4_U1 "IPW65R019C7" WP_TO247P#2 46.101,73.99 r0 bottom locked
Q4_U2 "IPW65R019C7" WP_TO247P#2 206.146,72.822 r0 bottom locked
Q5_U1 "IPW65R019C7" WP_TO247P#2 60.858,49.936 r180 bottom locked
Q5_U2 "IPW65R019C7" WP_TO247P#2 220.921,48.83 r180 bottom locked
Q6_U1 "MMBT4401" WP_SOT23B 86.309,111.912 r270 top (schematic designator Q6)
Q6_U2 "MMBT4401" WP_SOT23B 219.812,114.579 r270 top (schematic designator Q6)
Q7_U1 "IPW65R019C7" WP_TO247P#2 67.158,73.965 r0 bottom locked
Q7_U2 "IPW65R019C7" WP_TO247P#2 227.152,72.771 r0 bottom locked
Q8_U1 "IPW65R019C7" WP_TO247P#2 77.927,49.936 r180 bottom locked
Q8_U2 "IPW65R019C7" WP_TO247P#2 237.921,48.83 r180 bottom locked
R1_U1 "10K/0.1%" WP_0805R 1.753,51.892 r0 top (schematic designator R1)
R1_U2 "10K/0.1%" WP_0805R 149.047,114.452 r270 top (schematic designator R1)
R2_U1 "1K/0.1%" WP_0805R 6.375,51.892 r0 top (schematic designator R2)
R2_U2 "1K/0.1%" WP_0805R 148.996,109.982 r270 top (schematic designator R2)
R3_U1 "3K/0.1%" WP_0805R 12.573,60.452 r270 top (schematic designator R3)
R3_U2 "3K/0.1%" WP_0805R 147.726,104.8 r180 top (schematic designator R3)
R4_U1 "3K/0.1%" WP_0805R 14.757,60.325 r0 top (schematic designator R4)
R4_U2 "3K/0.1%" WP_0805R 145.72,102.438 r180 top (schematic designator R4)
R5_U1 "1K/0.1%" WP_0805R 1.626,63.805 r0 top (schematic designator R5)
R5_U2 "1K/0.1%" WP_0805R 147.345,117.119 r180 top (schematic designator R5)
R6_U1 "1K/0.1%" WP_0805R 6.325,65.862 r270 top (schematic designator R6)
R6_U2 "1K/0.1%" WP_0805R 137.617,112.217 r270 top (schematic designator R6)
R7_U1 "620R/0.1%" WP_0805R 12.548,53.619 r90 top (schematic designator R7)
R7_U2 "620R/0.1%" WP_0805R 143.256,104.8 r180 top (schematic designator R7)
R8_U1 "10K" WP_0805R 19.939,114.097 r270 top (schematic designator R8)
R8_U2 "10K" WP_0805R 226.187,113.462 r90 top (schematic designator R8)
R9_U1 "2K/0.1%" WP_0805R 1.676,66.04 r0 top (schematic designator R9)
R9_U2 "2K/0.1%" WP_0805R 140.259,117.119 r0 top (schematic designator R9)
R10_U1 "100R/0.1%" WP_0805R 14.808,53.619 r90 top (schematic designator R10)
R10_U2 "100R/0.1%" WP_0805R 138.735,102.54 r90 top (schematic designator R10)
R11_U1 "0R" WP_0805R 17.043,56.007 r270 top (schematic designator R11)
R11_U2 "0R" WP_0805R 138.709,98.044 r90 top (schematic designator R11)
R12_U1 "10K/0.1%" WP_0805R 6.35,68.097 r90 top (schematic designator R12)
R12_U2 "10K/0.1%" WP_0805R 137.719,114.173 r90 top (schematic designator R12)
R13_U1 "2K" WP_0805R 107.493,127.508 r180 top (schematic designator R13)
R13_U2 "2K" WP_0805R 168.859,120.066 r90 top (schematic designator R13)
R14_U1 "10K" WP_0805R 111.379,124.079 r180 top (schematic designator R14)
R14_U2 "10K" WP_0805R 171.247,122.453 r270 top (schematic designator R14)
R15_U1 "10K" WP_0805R 88.417,59.004 r0 top (schematic designator R15)
R15_U2 "10K" WP_0805R 167.742,71.755 r90 top (schematic designator R15)
R16_U1 "3K" WP_0805R 1.422,102.718 r270 top (schematic designator R16)
R16_U2 "3K" WP_0805R 258.572,117.018 r270 top (schematic designator R16)
R17_U1 "30K" WP_0805R 8.001,123.977 r180 top (schematic designator R17)
R17_U2 "30K" WP_0805R 235.001,118.339 r270 top (schematic designator R17)
R18_U1 "0K" WP_0805R 88.417,61.392 r0 top (schematic designator R18)
R18_U2 "0K" WP_0805R 169.824,71.78 r0 top (schematic designator R18)
R19_U1 "51K" WP_0805R 3.607,107.391 r270 top (schematic designator R19)
R19_U2 "51K" WP_0805R 250.825,112.344 r0 top (schematic designator R19)
R20_U1 "2K" WP_0805R 5.893,105.105 r0 top (schematic designator R20)
R20_U2 "2K" WP_0805R 253.009,114.579 r90 top (schematic designator R20)
R21_U1 "0R" WP_JS2L 113.182,88.976 r270 top (schematic designator R21)
R21_U2 "0R" WP_JS2L 145.237,88.9 r270 top (schematic designator R21)
R22_U1 "10K" WP_0805R 1.93,112.141 r270 top (schematic designator R22)
R22_U2 "10K" WP_0805R 244.043,112.573 r180 top (schematic designator R22)
R23_U1 "2R" WP_0805R 39.472,90.399 r270 top (schematic designator R23)
R23_U2 "2R" WP_0805R 199.492,88.087 r270 top (schematic designator R23)
R24_U1 "100K" WP_0805R 3.607,124.003 r180 top (schematic designator R24)
R24_U2 "100K" WP_0805R 232.664,115.926 r90 top (schematic designator R24)
R25_U1 "36K" WP_0805R 4.242,112.141 r270 top (schematic designator R25)
R25_U2 "36K" WP_0805R 246.075,112.522 r0 top (schematic designator R25)
R26_U1 "2R" WP_0805R 37.236,90.373 r270 top (schematic designator R26)
R26_U2 "2R" WP_0805R 197.231,88.113 r270 top (schematic designator R26)
R27_U1 "2R" WP_0805R 35.56,85.293 r270 top (schematic designator R27)
R27_U2 "2R" WP_0805R 195.453,82.474 r270 top (schematic designator R27)
R28_U1 "10K" WP_0805R 100.559,119.558 r180 top (schematic designator R28)
R28_U2 "10K" WP_0805R 159.156,116.713 r0 top (schematic designator R28)
R29_U1 "5K1" WP_0805R 102.768,119.456 r0 top (schematic designator R29)
R29_U2 "5K1" WP_0805R 163.678,116.713 r0 top (schematic designator R29)
R30_U1 "10K" WP_0805R 35.712,80.67 r180 top (schematic designator R30)
R30_U2 "10K" WP_0805R 195.605,77.927 r180 top (schematic designator R30)
R31_U1 "3K" WP_0805R 31.521,111.328 r90 top (schematic designator R31)
R31_U2 "3K" WP_0805R 192.634,109.728 r90 top (schematic designator R31)
R32_U1 "2R" WP_0805R 26.035,90.373 r270 top (schematic designator R32)
R32_U2 "2R" WP_0805R 185.953,88.062 r270 top (schematic designator R32)
R33_U1 "3K" WP_0805R 28.931,111.404 r180 top (schematic designator R33)
R33_U2 "3K" WP_0805R 190.195,109.804 r90 top (schematic designator R33)
R34_U1 "10K" WP_0805R 93.751,62.179 r270 top (schematic designator R34)
R34_U2 "10K" WP_0805R 178.105,84.76 r90 top (schematic designator R34)
R35_U1 "2R" WP_0805R 23.368,90.373 r270 top (schematic designator R35)
R35_U2 "2R" WP_0805R 183.693,88.138 r270 top (schematic designator R35)
R36_U1 "2R" WP_0805R 23.241,85.75 r270 top (schematic designator R36)
R36_U2 "2R" WP_0805R 183.617,83.541 r270 top (schematic designator R36)
R37_U1 "10K" WP_0805R 21.057,81.128 r0 top (schematic designator R37)
R37_U2 "10K" WP_0805R 181.407,78.943 r0 top (schematic designator R37)
R38_U1 "750R" WP_0805R 103.911,91.135 r270 top (schematic designator R38)
R38_U2 "750R" WP_0805R 175.311,98.933 r180 top (schematic designator R38)
R39_U1 "2R" WP_0805R 60.757,90.5 r270 top (schematic designator R39)
R39_U2 "2R" WP_0805R 220.37,88.24 r270 top (schematic designator R39)
R40_U1 "10R" WP_0805R 101.879,62.332 r270 top (schematic designator R40)
R40_U2 "10R" WP_0805R 167.792,80.848 r270 top (schematic designator R40)
R41_U1 "2R" WP_0805R 58.318,90.526 r270 top (schematic designator R41)
R41_U2 "2R" WP_0805R 218.11,88.189 r270 top (schematic designator R41)
R42_U1 "2R" WP_0805R 57.963,85.395 r270 top (schematic designator R42)
R42_U2 "2R" WP_0805R 215.951,82.093 r270 top (schematic designator R42)
R43_U1 "10K" WP_0805R 91.694,119.38 r180 top (schematic designator R43)
R43_U2 "10K" WP_0805R 174.498,121.59 r270 top (schematic designator R43)
R44_U1 "5K1" WP_0805R 86.893,119.304 r180 top (schematic designator R44)
R44_U2 "5K1" WP_0805R 176.708,117.018 r180 top (schematic designator R44)
R45_U1 "750R" WP_0805R 101.295,91.161 r270 top (schematic designator R45)
R45_U2 "750R" WP_0805R 170.358,101.168 r270 top (schematic designator R45)
R46_U1 "10K" WP_0805R 97.282,59.868 r90 top (schematic designator R46)
R46_U2 "10K" WP_0805R 172.212,74.016 r180 top (schematic designator R46)
R47_U1 "10K" WP_0805R 55.677,80.797 r0 top (schematic designator R47)
R47_U2 "10K" WP_0805R 213.665,77.521 r0 top (schematic designator R47)
R48_U1 "3K" WP_0805R 52.857,110.693 r90 top (schematic designator R48)
R48_U2 "3K" WP_0805R 211.811,109.271 r90 top (schematic designator R48)
R49_U1 "2R" WP_0805R 47.193,90.246 r270 top (schematic designator R49)
R49_U2 "2R" WP_0805R 207.01,88.189 r270 top (schematic designator R49)
R50_U1 "3K" WP_0805R 50.622,110.642 r90 top (schematic designator R50)
R50_U2 "3K" WP_0805R 209.55,109.271 r90 top (schematic designator R50)
R51_U1 "2K" WP_0805R 86.36,105.893 r180 top (schematic designator R51)
R51_U2 "2K" WP_0805R 223.749,113.462 r90 top (schematic designator R51)
R52_U1 "2R" WP_0805R 44.882,90.297 r270 top (schematic designator R52)
R52_U2 "2R" WP_0805R 204.724,88.189 r270 top (schematic designator R52)
R53_U1 "2R" WP_0805R 44.679,85.166 r270 top (schematic designator R53)
R53_U2 "2R" WP_0805R 204.724,82.906 r270 top (schematic designator R53)
R54_U1 "10K" WP_0805R 42.57,80.467 r0 top (schematic designator R54)
R54_U2 "10K" WP_0805R 202.387,78.181 r0 top (schematic designator R54)
R55_U1 "3K" WP_0805R 84.15,110.236 r90 top (schematic designator R55)
R55_U2 "3K" WP_0805R 220.269,117.653 r180 top (schematic designator R55)
R56_U1 "10K" WP_0805R 85.954,126.492 r180 top (schematic designator R56)
R56_U2 "10K" WP_0805R 187.325,116.992 r0 top (schematic designator R56)
R57_U1 "5K1" WP_0805R 84.201,124.206 r180 top (schematic designator R57)
R57_U2 "5K1" WP_0805R 189.636,119.304 r90 top (schematic designator R57)
R58_U1 "3K" WP_0805R 86.36,108.153 r180 top (schematic designator R58)
R58_U2 "3K" WP_0805R 215.113,114.427 r0 top (schematic designator R58)
R59_U1 "2R" WP_0805R 81.432,90.5 r270 top (schematic designator R59)
R59_U2 "2R" WP_0805R 241.884,88.24 r270 top (schematic designator R59)
R60_U1 "2R" WP_0805R 79.197,90.449 r270 top (schematic designator R60)
R60_U2 "2R" WP_0805R 239.42,88.214 r270 top (schematic designator R60)
R61_U1 "2R" WP_0805R 78.283,84.684 r270 top (schematic designator R61)
R61_U2 "2R" WP_0805R 239.116,83.363 r270 top (schematic designator R61)
R62_U1 "10K" WP_0805R 76.073,80.035 r0 top (schematic designator R62)
R62_U2 "10K" WP_0805R 236.779,78.689 r0 top (schematic designator R62)
R63_U1 "3K" WP_0805R 72.161,110.744 r90 top (schematic designator R63)
R63_U2 "3K" WP_0805R 231.724,109.449 r90 top (schematic designator R63)
R64_U1 "2R" WP_0805R 68.783,90.145 r270 top (schematic designator R64)
R64_U2 "2R" WP_0805R 227.813,88.57 r270 top (schematic designator R64)
R65_U1 "3K" WP_0805R 69.901,110.846 r180 top (schematic designator R65)
R65_U2 "3K" WP_0805R 229.514,109.449 r90 top (schematic designator R65)
R66_U1 "2R" WP_0805R 66.446,90.17 r270 top (schematic designator R66)
R66_U2 "2R" WP_0805R 225.298,88.468 r270 top (schematic designator R66)
R67_U1 "2R" WP_0805R 66.396,85.623 r270 top (schematic designator R67)
R67_U2 "2R" WP_0805R 225.12,83.541 r270 top (schematic designator R67)
R68_U1 "10K" WP_0805R 64.643,80.569 r0 top (schematic designator R68)
R68_U2 "10K" WP_0805R 222.936,78.943 r0 top (schematic designator R68)
R69_U1 "10K" WP_0805R 103.581,110.82 r270 top (schematic designator R69)
R69_U2 "10K" WP_0805R 250.292,104.623 r270 top (schematic designator R69)
R70_U1 "5K1" WP_0805R 101.397,108.433 r180 top (schematic designator R70)
R70_U2 "5K1" WP_0805R 250.241,100.228 r270 top (schematic designator R70)
R71_U1 "3K" WP_0805R 108.915,111.582 r0 top (schematic designator R71)
R71_U2 "3K" WP_0805R 137.82,118.796 r90 top (schematic designator R71)
R72_U1 "20K" WP_0805R 76.479,122.123 r0 top (schematic designator R72)
R72_U2 "20K" WP_0805R 249.301,94.945 r0 top (schematic designator R72)
R73_U1 "10K" WP_0805R 72.161,122.123 r0 top (schematic designator R73)
R73_U2 "10K" WP_0805R 251.612,92.202 r180 top (schematic designator R73)
R74_U1 "100K" WP_0805R 26.238,63.906 r0 top (schematic designator R74)
R74_U2 "100K" WP_0805R 237.998,61.595 r180 top (schematic designator R74)
R75_U1 "100K" WP_0805R 19.101,65.964 r90 top (schematic designator R75)
R75_U2 "100K" WP_0805R 242.773,70.612 r270 top (schematic designator R75)
R76_U1 "100K" WP_0805R 21.488,65.964 r90 top (schematic designator R76)
R76_U2 "100K" WP_0805R 242.697,63.779 r90 top (schematic designator R76)
R77_U1 "100K" WP_0805R 26.238,68.428 r270 top (schematic designator R77)
R77_U2 "100K" WP_0805R 237.871,66.167 r270 top (schematic designator R77)
R78_U1 "5K1/1%" WP_0805R 19.05,72.746 r0 top (schematic designator R78)
R78_U2 "5K1/1%" WP_0805R 251.993,75.209 r0 top (schematic designator R78)
R79_U1 "100K" WP_0805R 16.815,70.434 r90 top (schematic designator R79)
R79_U2 "100K" WP_0805R 247.371,72.771 r0 top (schematic designator R79)
R80_U1 "100K" WP_0805R 16.789,68.351 r270 top (schematic designator R80)
R80_U2 "100K" WP_0805R 245.186,72.796 r180 top (schematic designator R80)
R81_U1 "100K" WP_0805R 23.8,63.779 r180 top (schematic designator R81)
R81_U2 "100K" WP_0805R 240.259,61.57 r0 top (schematic designator R81)
R82_U1 "100K" WP_0805R 23.8,65.989 r90 top (schematic designator R82)
R82_U2 "100K" WP_0805R 240.284,63.779 r90 top (schematic designator R82)
R83_U1 "20K" WP_0805R 76.53,119.507 r0 top (schematic designator R83)
R83_U2 "20K" WP_0805R 253.848,94.92 r0 top (schematic designator R83)
R84_U1 "10K" WP_0805R 72.161,119.507 r0 top (schematic designator R84)
R84_U2 "10K" WP_0805R 254.025,92.177 r0 top (schematic designator R84)
R85_U1 "200R" WP_0805R 68.682,119.532 r180 top (schematic designator R85)
R85_U2 "200R" WP_0805R 191.872,118.847 r0 top (schematic designator R85)
R86_U1 "200R" WP_0805R 68.656,122.199 r180 top (schematic designator R86)
R86_U2 "200R" WP_0805R 191.872,116.611 r0 top (schematic designator R86)
T1_U1 "ACM7060-102" WP_ACM7060 93.396,92.202 r90 top (schematic designator T1)
T1_U2 "ACM7060-102" WP_ACM7060 170.307,105.283 r180 top (schematic designator T1)
U1_U1 "MCP604T-I/SL" WP_SOIC14 1.245,55.804 r90 top (schematic designator U1)
U1_U2 "MCP604T-I/SL" WP_SOIC14 141.503,115.646 r0 top (schematic designator U1)
U2_U1 "AS1117-2V5" WP_SOT223 12.065,44.806 r180 top (schematic designator U2)
U2_U2 "AS1117-2V5" WP_SOT223 129.794,105.664 r90 top (schematic designator U2)
U3_U1 "TPS54531DDAR" WP_SOIC8P 9.017,121.133 r270 top (schematic designator U3)
U3_U2 "TPS54531DDAR" WP_SOIC8P 237.338,118.516 r0 top (schematic designator U3)
U4_U1 "OPA2188AIDR" WP_SOIC8 101.981,126.086 r0 top (schematic designator U4)
U4_U2 "OPA2188AIDR" WP_SOIC8 161.62,123.292 r0 top (schematic designator U4)
U5_U1 "ACS712ELCTR-20B-T" WP_SOIC8 80.899,56.439 r180 top (schematic designator U5)
U5_U2 "ACS712ELCTR-20B-T" WP_SOIC8 166.218,61.087 r0 top (schematic designator U5)
U6_U1 "IR2213S" WP_SOIC16L 26.772,97.942 r90 top (schematic designator U6)
U6_U2 "IR2213S" WP_SOIC16L 187.655,96.52 r90 top (schematic designator U6)
U7_U1 "ACS712ELCTR-20B-T" WP_SOIC8 34.29,45.847 r0 top (schematic designator U7)
U7_U2 "ACS712ELCTR-20B-T" WP_SOIC8 192.227,44.755 r0 top (schematic designator U7)
U8_U1 "OPA2188AIDR" WP_SOIC8 92.634,121.006 r180 top (schematic designator U8)
U8_U2 "OPA2188AIDR" WP_SOIC8 180.391,123.571 r0 top (schematic designator U8)
U9_U1 "IR2213S" WP_SOIC16L 47.777,97.942 r90 top (schematic designator U9)
U9_U2 "IR2213S" WP_SOIC16L 207.239,96.52 r90 top (schematic designator U9)
U10_U1 "ACS712ELCTR-20B-T" WP_SOIC8 59.588,45.822 r0 top (schematic designator U10)
U10_U2 "ACS712ELCTR-20B-T" WP_SOIC8 216.941,44.679 r0 top (schematic designator U10)
U11_U1 "IR2213S" WP_SOIC16L 67.488,97.968 r90 top (schematic designator U11)
U11_U2 "IR2213S" WP_SOIC16L 227.508,96.495 r90 top (schematic designator U11)
U12_U1 "ACS712ELCTR-20B-T" WP_SOIC8 76.098,45.72 r0 top (schematic designator U12)
U12_U2 "ACS712ELCTR-20B-T" WP_SOIC8 234.239,44.679 r0 top (schematic designator U12)
U13_U1 "OPA2188AIDR" WP_SOIC8 98.577,112.065 r180 top (schematic designator U13)
U13_U2 "OPA2188AIDR" WP_SOIC8 257.226,102.489 r270 top (schematic designator U13)
U14_U1 "ACPL-C87B-500E" WP_SOIC8L 15.24,88.163 r90 top (schematic designator U14)
U14_U2 "ACPL-C87B-500E" WP_SOIC8L 251.79,78.08 r90 top (schematic designator U14)
U15 "LRM5-A60H12RB-T2" WP_LRM5-A60H12RB-T2 101,-2.997 r0 top locked
U16_U1 "TLP127" WP_SOP4 64.237,119.659 r180 top (schematic designator U16)
U16_U2 "TLP127" WP_SOP4 196.571,119.101 r0 top (schematic designator U16)
U17_U1 "TLP358H" WP_SOP8 106.451,85.319 r270 top (schematic designator U17)
U17_U2 "TLP358H" WP_SOP8 175.641,95.682 r270 top (schematic designator U17)
V1_U1 "BAV99" WP_SOT23B 18.39,83.896 r180 top (schematic designator V1)
V1_U2 "BAV99" WP_SOT23B 258.318,73.076 r90 top (schematic designator V1)

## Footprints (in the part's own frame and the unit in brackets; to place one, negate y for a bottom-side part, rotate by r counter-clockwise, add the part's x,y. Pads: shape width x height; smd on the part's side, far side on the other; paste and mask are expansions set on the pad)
DC12-12 [mil]
  round 60 hole 30: 1(0,0) 2(100,0) 3(400,0) 4(600,0)
  silkscreen extent -85,-250 695,120
MKP3D-450V-140UF-1 [mm]
  round 6 hole 3.2: 0(3,49) 0(10,-4) 0(81,-4) 0(87,49)
  oval 5x4 hole 2: 1(6,6) 1(46,39) 2(55,39) 2(60,6)
  silkscreen extent 0,-7 90,52
WP_0805_LED [mil]
  rect 50x50 smd: 1(0,0) 2(91,0)
  silkscreen extent -33,-37 138,36
WP_0805C [mil]
  rect 39.37x50 smd: 1(1,-1) 2(95,-1)
  silkscreen extent -30,-38 125,35
WP_0805R [mm]
  rect 1x1.27 smd: 1(0,0) 2(2.388,0)
  silkscreen extent -0.79,-0.94 3.17,0.91
WP_1206CC [mil]
  rect 52.13x60 smd: 1(0,0) 2(135,0)
  silkscreen extent -36,-43 171,42
WP_1210CC [mil]
  rect 60x100 smd: 1(0,0) 2(135,0)
  silkscreen extent -44,-63 179,63
WP_1812 [mm]
  rect 2x3.175 smd: 1(-0.152,0) 2(4.343,0)
  silkscreen extent -1.52,-2.16 5.71,2.16
WP_1812D [mil]
  rect 60x125 smd: 1(0,0) 2(185,0)
  silkscreen extent -46,-85 232,85
WP_ACM7060 [mm]
  rect 2x1.5 smd: 1(0,0.051) 2(7,0.051) 3(0.025,-2.949) 4(7,-2.949)
  silkscreen extent -0.99,-4.42 8,1.52
WP_CRM222-030 [mil]
  oval 40x60 hole 30: 1(0,0) 2(-75,0) 3(-150,0) 4(-225,0) 5(-300,0) 6(-375,0) 7(-450,0) 8(-525,0) 9(-600,0) 10(-675,0) 11(-750,0) 12(-825,0) 13(-900,0) 14(-975,0) 15(-1050,0) 16(-37.48,75) 17(-112.48,75) 18(-187.48,75) 19(-262.48,75) 20(-337.48,75) 21(-412.48,75) 22(-487.48,75) 23(-562.48,75) 24(-637.48,75) 25(-712.48,75) 26(-787.48,75) 27(-862.48,75) 28(-937.48,75) 29(-1012.48,75) 30(-1087.48,75)
  round 106.3 hole 106.3: ""(-1402.48,37.5) ""(314.04,37.5)
  silkscreen extent -1489,-63 401,138
WP_JS2L [mm]
  rect 3x5 smd: 1(-0.102,-0.025) 2(3.581,-0.025)
  silkscreen extent -1.78,-2.69 5.26,2.64
WP_LBS6*6 [mm]
  rect 2x3.5 smd: 1(0,0) 2(5.5,0)
  silkscreen extent -1.19,-3 6.71,3
WP_LRM5-A60H12RB-T2 [mm]
  oval 2.8x3.5 hole 2.3: 1(32.7,7.66) 2(37.9,7.66) 3(43.1,7.66) 4(48.3,7.66) 5(53.5,7.66) 6(58.7,7.66) 7(32.7,2.16) 8(37.9,2.16) 9(43.1,2.16) 10(48.3,2.16) 11(53.5,2.16) 12(58.7,2.16)
  oval 0.9x1.016 hole 0.6: A1(5.7,-3.63) A2(7.7,-3.63) A3(9.7,-3.63) A4(11.7,-3.63) A5(13.7,-3.63) A6(15.7,-3.63) A7(17.7,-3.63) A8(19.7,-3.63) A9(21.7,-3.63) A10(23.7,-3.63) A11(25.7,-3.63) A12(27.7,-3.63) B1(5.7,-1.63) B2(7.7,-1.63) B3(9.7,-1.63) B4(11.7,-1.63) B5(13.7,-1.63) B6(15.7,-1.63) B7(17.7,-1.63) B8(19.7,-1.63) B9(21.7,-1.63) B10(23.7,-1.63) B11(25.7,-1.63) B12(27.7,-1.63) C1(5.7,0.37) C2(7.7,0.37) C3(9.7,0.37) C4(11.7,0.37) C5(13.7,0.37) C6(15.7,0.37) C7(17.7,0.37) C8(19.7,0.37) C9(21.7,0.37) C10(23.7,0.37) C11(25.7,0.37) C12(27.7,0.37) D1(5.7,2.37) D2(7.7,2.37) D3(9.7,2.37) D4(11.7,2.37) D5(13.7,2.37) D6(15.7,2.37) D7(17.7,2.37) D8(19.7,2.37) D9(21.7,2.37) D10(23.7,2.37) D11(25.7,2.37) D12(27.7,2.37) E1(5.7,4.37) E2(7.7,4.37) E3(9.7,4.37) E4(11.7,4.37) E5(13.7,4.37) E6(15.7,4.37) E7(17.7,4.37) E8(19.7,4.37) E9(21.7,4.37) E10(23.7,4.37) E11(25.7,4.37) E12(27.7,4.37)
  round 5 hole 2.7: ""(0,0) ""(65.4,0)
  silkscreen extent -3.68,-20 69.12,11.43
WP_LSIP2 [mil]
  rect 100x100 hole 60: 1(0,0)
  round 100 hole 60: 2(150,0)
  silkscreen extent -106,-136 252,142
WP_SIP2 [mil]
  rect 70x70 hole 40: 1(0,0)
  round 70 hole 40: 2(100,0)
  silkscreen extent -50,-120 160,100
WP_SMA_DO214AC [mm]
  rect 2.35x1.55 smd: 1(0,0) 2(4.3,0)
  silkscreen extent -0.65,-1.5 5.73,1.5, body extent -0.45,-1.3 4.75,1.3, height 2.64
WP_SOIC8 [mm]
  oval 1.5x0.5 smd: 1(-1.473,-0.66) 2(-1.473,-1.93) 3(-1.473,-3.2) 4(-1.473,-4.47) 5(4.674,-4.47) 6(4.674,-3.2) 7(4.674,-1.93) 8(4.674,-0.66)
  silkscreen extent -0.03,-5.08 3.23,0.03
WP_SOIC8L [mm]
  oval 2x0.6 smd: 1(0,0) 2(0,-1.27) 3(0,-2.54) 4(0,-3.81) 5(11.506,-3.81) 6(11.506,-2.54) 7(11.506,-1.27) 8(11.506,0)
  silkscreen extent 1.45,-4.42 10.06,0.69
WP_SOIC8P [mil]
  oval 59.06x19.68 smd: 1(-2,1) 2(-2,-49) 3(-2,-99) 4(-2,-149) 5(240,-149) 6(240,-99) 7(240,-49) 8(240,1)
  rect 100x120 smd: 9(119,-73)
  silkscreen extent 55,-173 183,28
WP_SOIC14 [mm]
  oval 1.5x0.5 smd: 1(-1.219,-0.889) 2(-1.219,-2.159) 3(-1.219,-3.429) 4(-1.219,-4.699) 5(-1.219,-5.969) 6(-1.219,-7.239) 7(-1.219,-8.509) 8(4.953,-8.484) 9(4.928,-7.214) 10(4.928,-5.994) 11(4.928,-4.674) 12(4.928,-3.404) 13(4.928,-2.159) 14(4.928,-0.864)
  silkscreen extent 0.03,-9.12 3.68,0.05
WP_SOIC16L [mm]
  rect 2x0.4 smd: 1(0,0)
  oval 2x0.4 smd: 2(0,-1.27) 3(0,-2.54) 4(0,-3.81) 5(0,-5.08) 6(0,-6.35) 7(0,-7.62) 8(0,-8.89) 9(10.65,-8.89) 10(10.65,-7.62) 11(10.65,-6.35) 12(10.65,-5.08) 13(10.65,-3.81) 14(10.65,-2.54) 15(10.65,-1.27) 16(10.65,0)
  silkscreen extent 1.84,-9.53 8.81,0.64
WP_SOP4 [mil]
  rect 80x30 smd: 1(11,1)
  oval 80x30 smd: 3(11,-99) 4(293,-99) 6(293,1)
  silkscreen extent 63,-140 241,51
WP_SOP8 [mil]
  rect 100x50 smd: 1(0,0)
  oval 100x50 smd: 2(0,-100) 3(0,-200) 4(0,-300) 5(403,-300) 6(403,-200) 7(403,-100) 8(403,0)
  silkscreen extent 104,-350 305,50
WP_SOT23B [mil]
  rect 30x40 smd: 1(0,0) 2(74,0) 3(37,76)
  silkscreen extent -19,-24 93,100
WP_SOT223 [mm]
  rect 1x1.8 smd: 1(0.864,-4.47) 2(3.175,-4.47) 3(5.436,-4.496)
  rect 4x2.4 smd: 4(3.15,1.473)
  silkscreen extent 0,-3.35 6.27,0
WP_TO247P#1 [mm]
  rect 2x3.5 hole 1.8: 1(0,0)
  oval 2x3.5 hole 1.8: 2(5.44,0) 3(10.88,0)
  round 4 hole 2.2: ""(5.465,20)
  silkscreen extent -2.54,-2.74 13.41,25.91
WP_TO247P#2 [mm]
  rect 2x3.5 hole 1.8: 1(0,0)
  oval 2x3.5 hole 1.8: 2(5.44,0) 3(10.88,0)
  round 4 hole 2.2: ""(5.465,-20)
  silkscreen extent -2.54,-25.91 13.41,2.74

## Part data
C1_U1 C1_U2 C2_U1 C2_U2: library part ELECTRO1, "Electrolytic Capacitor"
C3_U1 C3_U2 C4_U1 C4_U2 C12_U1 C12_U2 C14_U1 C14_U2 C19_U1 C19_U2 C31_U1 C31_U2 C32_U1 C32_U2 C33_U1 C33_U2 C42_U1 C42_U2 C43_U1 C43_U2 C44_U1 C44_U2 C45_U1 C45_U2 C46_U1 C46_U2 C48_U1 C48_U2 C50_U1 C50_U2 C51_U1 C51_U2 C52_U1 C52_U2 C53_U1 C53_U2 C61_U1 C61_U2 C64_U1 C64_U2 C67_U1 C67_U2 C68_U1 C68_U2: library part CAP, "Capacitor"
C4: library part "Cap Pol1", "Polarized Capacitor (Radial)"
C5_U1 C5_U2 C6_U1 C6_U2 C24_U1 C24_U2 C34_U1 C34_U2 C35_U1 C35_U2 C36_U1 C36_U2 C37_U1 C37_U2 C38_U1 C38_U2 C39_U1 C39_U2 C40_U1 C40_U2 C41_U1 C41_U2 C49_U1 C49_U2 C55_U1 C55_U2 C56_U1 C56_U2 C57_U1 C57_U2 C66_U1 C66_U2: library part Cap2, "Capacitor"
C7_U1 C7_U2 C8_U1 C8_U2 C9_U1 C9_U2 C10_U1 C10_U2 C11_U1 C11_U2 C13_U1 C13_U2 C15_U1 C15_U2 C16_U1 C16_U2 C17 C18 C20_U1 C20_U2 C23_U1 C23_U2 C25_U1 C25_U2 C29_U1 C29_U2 C30_U1 C30_U2 C58_U1 C58_U2 C59_U1 C59_U2 C60_U1 C60_U2 C69_U1 C69_U2 C70_U1 C70_U2 C71_U1 C71_U2 C72_U1 C72_U2 C73 C74 C75 C76 C77_U1 C77_U2 C78_U1 C78_U2: library part "Cap Semi", "Capacitor (Semiconductor SIM Model)"
C21_U1 C21_U2 C22_U1 C22_U2 C65_U1 C65_U2: library part CAP1
C26_U1 C26_U2 C27_U1 C27_U2 C28_U1 C28_U2: library part Cap, "Capacitor"
C47_U1 C47_U2 C54_U1 C54_U2: "Capacitor (Semiconductor SIM Model)"
C62_U1 C62_U2 C63_U1 C63_U2: library part CAP
D1_U1 D1_U2: library part LED2
D2_U1 D2_U2 D5_U1 D5_U2 D9_U1 D9_U2 D10_U1 D10_U2 D14_U1 D14_U2 D15_U1 D15_U2 D18_U1 D18_U2: library part "DIODE SCHOTTKY", "Schottky Diode"
D3_U1 D3_U2 D8_U1 D8_U2 D13_U1 D13_U2 D19_U1 D19_U2: library part LED0, "Typical INFRARED GaAs LED"
D6_U1 D6_U2 D7_U1 D7_U2 D11_U1 D11_U2 D12_U1 D12_U2 D16_U1 D16_U2 D17_U1 D17_U2: library part Diode, "Default Diode"
L1_U1 L1_U2: library part Inductor, "Inductor"
P1_U1 P1_U2 P2_U1 P2_U2: "Header, 2-Pin"
P3_U1 P3_U2: library part DC12-12
P4_U1 P4_U2: "Header, 15-Pin, Dual row"
Q1_U1 Q1_U2 Q2_U1 Q2_U2 Q3_U1 Q3_U2 Q4_U1 Q4_U2 Q5_U1 Q5_U2 Q7_U1 Q7_U2 Q8_U1 Q8_U2: library part 7N60
R1_U1 R1_U2 R2_U1 R2_U2 R3_U1 R3_U2 R4_U1 R4_U2 R5_U1 R5_U2 R6_U1 R6_U2 R7_U1 R7_U2 R8_U1 R8_U2 R9_U1 R9_U2 R10_U1 R10_U2 R11_U1 R11_U2 R12_U1 R12_U2 R13_U1 R13_U2 R14_U1 R14_U2 R15_U1 R15_U2 R18_U1 R18_U2 R21_U1 R21_U2 R23_U1 R23_U2 R26_U1 R26_U2 R27_U1 R27_U2 R28_U1 R28_U2 R29_U1 R29_U2 R30_U1 R30_U2 R32_U1 R32_U2 R35_U1 R35_U2 R36_U1 R36_U2 R37_U1 R37_U2 R39_U1 R39_U2 R40_U1 R40_U2 R41_U1 R41_U2 R42_U1 R42_U2 R43_U1 R43_U2 R44_U1 R44_U2 R47_U1 R47_U2 R49_U1 R49_U2 R52_U1 R52_U2 R53_U1 R53_U2 R54_U1 R54_U2 R56_U1 R56_U2 R57_U1 R57_U2 R59_U1 R59_U2 R60_U1 R60_U2 R61_U1 R61_U2 R62_U1 R62_U2 R64_U1 R64_U2 R66_U1 R66_U2 R67_U1 R67_U2 R68_U1 R68_U2 R69_U1 R69_U2 R70_U1 R70_U2 R72_U1 R72_U2 R73_U1 R73_U2 R74_U1 R74_U2 R75_U1 R75_U2 R76_U1 R76_U2 R77_U1 R77_U2 R78_U1 R78_U2 R79_U1 R79_U2 R80_U1 R80_U2 R81_U1 R81_U2 R82_U1 R82_U2 R83_U1 R83_U2 R84_U1 R84_U2: library part Res2, "Resistor"
R16_U1 R16_U2 R17_U1 R17_U2 R19_U1 R19_U2 R20_U1 R20_U2 R22_U1 R22_U2 R24_U1 R24_U2 R25_U1 R25_U2 R31_U1 R31_U2 R33_U1 R33_U2 R34_U1 R34_U2 R46_U1 R46_U2 R48_U1 R48_U2 R50_U1 R50_U2 R51_U1 R51_U2 R55_U1 R55_U2 R58_U1 R58_U2 R63_U1 R63_U2 R65_U1 R65_U2 R71_U1 R71_U2 R85_U1 R85_U2 R86_U1 R86_U2: library part RES
R38_U1 R38_U2 R45_U1 R45_U2: library part WP_RES
T1_U1 T1_U2: library part Trans, "Transformer"
U1_U1 U1_U2: library part TL084D, "JFET-Input Operational Amplifier"
U2_U1 U2_U2: library part AS1117
U4_U1 U4_U2 U8_U1 U8_U2 U13_U1 U13_U2: library part LT1358, "Fast Settling Dual Operational Amplifier"
U5_U1 U5_U2 U7_U1 U7_U2 U10_U1 U10_U2 U12_U1 U12_U2: library part ACS711
U15: library part MULTI_HEADER
U16_U1 U16_U2: library part TLP521-1
U17_U1 U17_U2: library part TLP358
